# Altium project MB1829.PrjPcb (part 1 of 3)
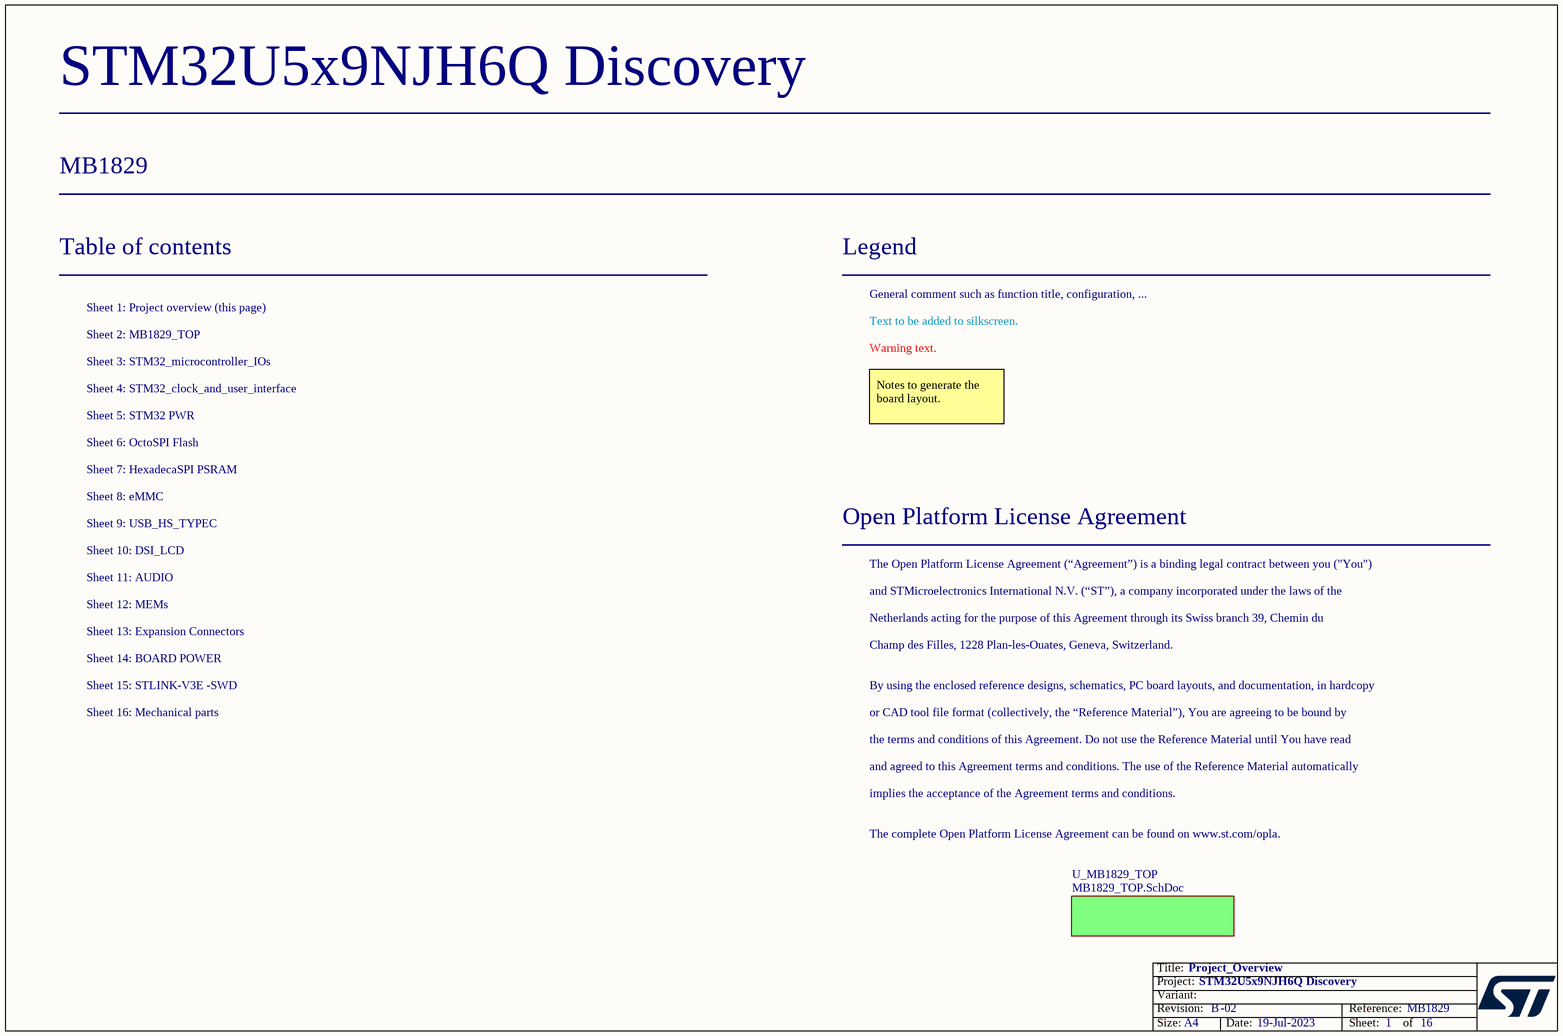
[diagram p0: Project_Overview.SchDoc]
Board_Assembly_Revision: 02; Board_Document_Date: 19-Jul-2023; Board_Name: STM32U5x9NJH6Q Discovery; Board_PCB_Revision: B; Board_Reference: MB1829
16 sheets, 473 parts. Net scope: flat (ports and power ports of the same name join across sheets).
Board file: MB1829.PcbDoc
Sheets:
  Project_Overview.SchDoc
    U_MB1829_TOP = MB1829_TOP.SchDoc
      U_EXPANSION_CONNECTORS = EXPANSION_CONNECTORS.SchDoc
      U_AUDIO = AUDIO.SchDoc
      U_BOARD_POWER = BOARD_POWER.SchDoc
      U_MCU_CLOCK_AND_USER_INTERFACE = MCU_CLOCK_AND_USER_INTERFACE.SchDoc
      U_MCU_IO = MCU_IO.SchDoc
      U_MCU_PWR = MCU_PWR.SchDoc
      U_MECHANICAL = MECHANICAL.SchDoc
      U_OCTOSPI_FLASH = OCTOSPI_FLASH.SchDoc
      U_ST_LINK_V3E = ST_LINK_V3E.SchDoc
      U_USBHS_TYPEC = USBHS_TYPEC.SchDoc
      U_eMMC = eMMC.SchDoc
      U_HEXADECASPI_PSRAM = HEXADECASPI_PSRAM.SchDoc
      U_DSI_LCD = DSI_LCD.SchDoc
      U_MEMS = MEMS.SchDoc

## Sheet Project_Overview.SchDoc: Project_Overview
size A4; Date: Not used; ApprovedBy: Not used; CheckedBy: Not used; Author: Not used; CompanyName: STMicroelectronics; DrawnBy: Not used; Engineer: Not used; Organization: Not used; Address1: Not used; Address2: Not used; Address3: Not used; Address4: Not used; DocumentNumber: Not used; Revision: Not used; SheetNumber: 1; SheetTotal: 16

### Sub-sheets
U_MB1829_TOP = MB1829_TOP.SchDoc: no entries

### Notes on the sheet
- Table of contents
- Sheet 1: Project overview (this page)
- Legend
- General comment such as function title, configuration, ...
- Sheet 2: MB1829_TOP
- Sheet 3: STM32_microcontroller_IOs
- Text to be added to silkscreen.
- Warning text.
- Sheet 4: STM32_clock_and_user_interface
- Sheet 6: OctoSPI Flash
- Sheet 5: STM32 PWR
- Notes to generate the board layout.
- Sheet 8: eMMC
- Sheet 7: HexadecaSPI PSRAM
- Sheet 10: DSI_LCD
- Sheet 11: AUDIO
- Sheet 9: USB_HS_TYPEC
- Open Platform License Agreement
- The Open Platform License Agreement (“Agreement”) is a binding legal contract between you ("You")
- Sheet 13: Expansion Connectors
- Sheet 12: MEMs
- and STMicroelectronics International N.V. (“ST”), a company incorporated under the laws of the
- Netherlands acting for the purpose of this Agreement through its Swiss branch 39, Chemin du
- Champ des Filles, 1228 Plan-les-Ouates, Geneva, Switzerland.
- Sheet 15: STLINK-V3E -SWD
- Sheet 16: Mechanical parts
- Sheet 14: BOARD POWER
- By using the enclosed reference designs, schematics, PC board layouts, and documentation, in hardcopy
- or CAD tool file format (collectively, the “Reference Material”), You are agreeing to be bound by
- the terms and conditions of this Agreement. Do not use the Reference Material until You have read
- and agreed to this Agreement terms and conditions. The use of the Reference Material automatically
- implies the acceptance of the Agreement terms and conditions.
- The complete Open Platform License Agreement can be found on www.st.com/opla.

## Sheet MB1829_TOP.SchDoc: MB1829 TOP
size A4; Date: Not used; ApprovedBy: Not used; CheckedBy: Not used; Author: Not used; CompanyName: STMicroelectronics; DrawnBy: Not used; Engineer: Not used; Organization: Not used; Address1: Not used; Address2: Not used; Address3: Not used; Address4: Not used; DocumentNumber: Not used; Revision: Not used; SheetNumber: 2; SheetTotal: 16
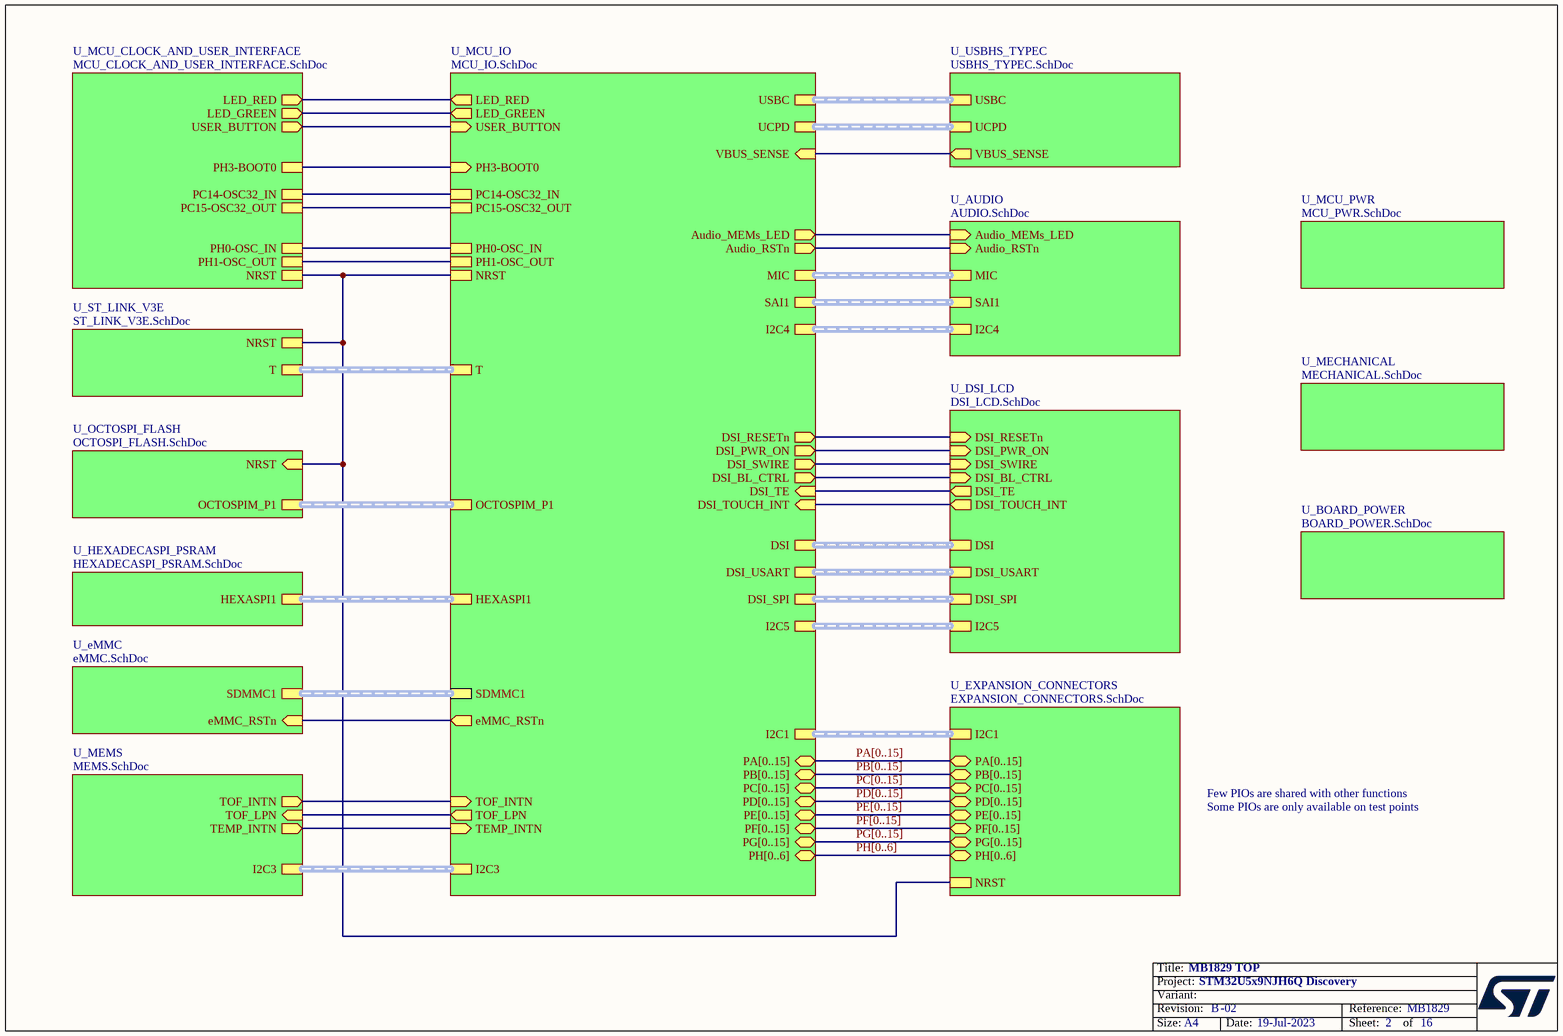
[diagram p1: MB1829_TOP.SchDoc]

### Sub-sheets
U_AUDIO = AUDIO.SchDoc: MIC (harness MIC), I2C4 (harness I2C4), SAI1 (harness SAI), Audio_RSTn (in), Audio_MEMs_LED (in)
U_BOARD_POWER = BOARD_POWER.SchDoc: no entries
U_DSI_LCD = DSI_LCD.SchDoc: DSI_RESETn (in), DSI_PWR_ON (in), DSI_SWIRE (in), DSI_BL_CTRL (in), DSI_TE (out), DSI_TOUCH_INT (out), DSI (harness DSI_LANES), I2C5 (harness I2C5), DSI_USART (harness DSI_USART), DSI_SPI (harness DSI_SPI)
U_eMMC = eMMC.SchDoc: eMMC_RSTn (in), SDMMC1 (harness eMMC)
U_EXPANSION_CONNECTORS = EXPANSION_CONNECTORS.SchDoc: NRST, I2C1 (harness I2C1), PC[0..15] (bidir), PA[0..15] (bidir), PB[0..15] (bidir), PD[0..15] (bidir), PE[0..15] (bidir), PH[0..6] (bidir), PF[0..15] (bidir), PG[0..15] (bidir)
U_HEXADECASPI_PSRAM = HEXADECASPI_PSRAM.SchDoc: HEXASPI1 (harness HEXASPI1)
U_MCU_CLOCK_AND_USER_INTERFACE = MCU_CLOCK_AND_USER_INTERFACE.SchDoc: NRST, PH3-BOOT0, PC14-OSC32_IN, PC15-OSC32_OUT, LED_RED (out), LED_GREEN (out), PH0-OSC_IN, PH1-OSC_OUT, USER_BUTTON (out)
U_MCU_IO = MCU_IO.SchDoc: PH3-BOOT0 (in), NRST, PH0-OSC_IN, PH1-OSC_OUT, PC14-OSC32_IN, PC15-OSC32_OUT, LED_RED (out), LED_GREEN (out), OCTOSPIM_P1 (harness OCTOSPI1), USBC (harness USBC), MIC (harness MIC), T (harness T), HEXASPI1 (harness HEXASPI1), SDMMC1 (harness eMMC), eMMC_RSTn (out), I2C4 (harness I2C4), SAI1 (harness SAI), USER_BUTTON (in), Audio_RSTn (out), I2C5 (harness I2C5), DSI_RESETn (out), DSI_PWR_ON (out), DSI_SWIRE (out), DSI_BL_CTRL (out), DSI_TE (in), DSI_TOUCH_INT (in), DSI_SPI (harness DSI_SPI), DSI_USART (harness DSI_USART), DSI (harness DSI_LANES), UCPD (harness UCPD_CTRL), VBUS_SENSE (in), PA[0..15] (bidir), PC[0..15] (bidir), PB[0..15] (bidir), PD[0..15] (bidir), PE[0..15] (bidir), PH[0..6] (bidir), PF[0..15] (bidir), PG[0..15] (bidir), I2C1 (harness I2C1), I2C3 (harness I2C3), TOF_INTN (in), TEMP_INTN (in), TOF_LPN (out), Audio_MEMs_LED (out)
U_MCU_PWR = MCU_PWR.SchDoc: no entries
U_MECHANICAL = MECHANICAL.SchDoc: no entries
U_MEMS = MEMS.SchDoc: I2C3 (harness I2C3), TOF_INTN (out), TOF_LPN (in), TEMP_INTN (out)
U_OCTOSPI_FLASH = OCTOSPI_FLASH.SchDoc: NRST (in), OCTOSPIM_P1 (harness OCTOSPI1)
U_ST_LINK_V3E = ST_LINK_V3E.SchDoc: NRST, T (harness T)
U_USBHS_TYPEC = USBHS_TYPEC.SchDoc: USBC (harness USBC), UCPD (harness UCPD_CTRL), VBUS_SENSE (out)

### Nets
(unnamed): sheet U_EXPANSION_CONNECTORS/NRST, sheet U_MCU_CLOCK_AND_USER_INTERFACE/NRST, sheet U_MCU_IO/NRST, sheet U_OCTOSPI_FLASH/NRST, sheet U_ST_LINK_V3E/NRST
(unnamed): sheet U_AUDIO/Audio_RSTn, sheet U_MCU_IO/Audio_RSTn  [a separate net that carries the same name]
(unnamed): sheet U_AUDIO/Audio_MEMs_LED, sheet U_MCU_IO/Audio_MEMs_LED  [a separate net that carries the same name]
(unnamed): sheet U_MCU_CLOCK_AND_USER_INTERFACE/PH3-BOOT0, sheet U_MCU_IO/PH3-BOOT0  [a separate net that carries the same name]
(unnamed): sheet U_MCU_CLOCK_AND_USER_INTERFACE/PC14-OSC32_IN, sheet U_MCU_IO/PC14-OSC32_IN  [a separate net that carries the same name]
(unnamed): sheet U_MCU_CLOCK_AND_USER_INTERFACE/PC15-OSC32_OUT, sheet U_MCU_IO/PC15-OSC32_OUT  [a separate net that carries the same name]
(unnamed): sheet U_MCU_CLOCK_AND_USER_INTERFACE/LED_RED, sheet U_MCU_IO/LED_RED  [a separate net that carries the same name]
(unnamed): sheet U_MCU_CLOCK_AND_USER_INTERFACE/LED_GREEN, sheet U_MCU_IO/LED_GREEN  [a separate net that carries the same name]
(unnamed): sheet U_MCU_CLOCK_AND_USER_INTERFACE/PH0-OSC_IN, sheet U_MCU_IO/PH0-OSC_IN  [a separate net that carries the same name]
(unnamed): sheet U_MCU_CLOCK_AND_USER_INTERFACE/PH1-OSC_OUT, sheet U_MCU_IO/PH1-OSC_OUT  [a separate net that carries the same name]
(unnamed): sheet U_MCU_CLOCK_AND_USER_INTERFACE/USER_BUTTON, sheet U_MCU_IO/USER_BUTTON  [a separate net that carries the same name]
(unnamed): sheet U_MCU_IO/eMMC_RSTn, sheet U_eMMC/eMMC_RSTn  [a separate net that carries the same name]
(unnamed): sheet U_MCU_IO/DSI_RESETn, sheet U_DSI_LCD/DSI_RESETn  [a separate net that carries the same name]
(unnamed): sheet U_MCU_IO/DSI_PWR_ON, sheet U_DSI_LCD/DSI_PWR_ON  [a separate net that carries the same name]
(unnamed): sheet U_MCU_IO/DSI_SWIRE, sheet U_DSI_LCD/DSI_SWIRE  [a separate net that carries the same name]
(unnamed): sheet U_MCU_IO/DSI_BL_CTRL, sheet U_DSI_LCD/DSI_BL_CTRL  [a separate net that carries the same name]
(unnamed): sheet U_MCU_IO/DSI_TE, sheet U_DSI_LCD/DSI_TE  [a separate net that carries the same name]
(unnamed): sheet U_MCU_IO/DSI_TOUCH_INT, sheet U_DSI_LCD/DSI_TOUCH_INT  [a separate net that carries the same name]
(unnamed): sheet U_MCU_IO/VBUS_SENSE, sheet U_USBHS_TYPEC/VBUS_SENSE  [a separate net that carries the same name]
(unnamed): sheet U_MCU_IO/TOF_INTN, sheet U_MEMS/TOF_INTN  [a separate net that carries the same name]
(unnamed): sheet U_MCU_IO/TEMP_INTN, sheet U_MEMS/TEMP_INTN  [a separate net that carries the same name]
(unnamed): sheet U_MCU_IO/TOF_LPN, sheet U_MEMS/TOF_LPN  [a separate net that carries the same name]

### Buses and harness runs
bus PA[0..15] = sheet U_EXPANSION_CONNECTORS/PA[0..15] = sheet U_MCU_IO/PA[0..15]
bus PB[0..15] = sheet U_EXPANSION_CONNECTORS/PB[0..15] = sheet U_MCU_IO/PB[0..15]
bus PC[0..15] = sheet U_EXPANSION_CONNECTORS/PC[0..15] = sheet U_MCU_IO/PC[0..15]
bus PD[0..15] = sheet U_EXPANSION_CONNECTORS/PD[0..15] = sheet U_MCU_IO/PD[0..15]
bus PE[0..15] = sheet U_EXPANSION_CONNECTORS/PE[0..15] = sheet U_MCU_IO/PE[0..15]
bus PF[0..15] = sheet U_EXPANSION_CONNECTORS/PF[0..15] = sheet U_MCU_IO/PF[0..15]
bus PG[0..15] = sheet U_EXPANSION_CONNECTORS/PG[0..15] = sheet U_MCU_IO/PG[0..15]
bus PH[0..6] = sheet U_EXPANSION_CONNECTORS/PH[0..6] = sheet U_MCU_IO/PH[0..6]
harness sheet U_AUDIO/I2C4 = sheet U_MCU_IO/I2C4
harness sheet U_AUDIO/MIC = sheet U_MCU_IO/MIC
harness sheet U_AUDIO/SAI1 = sheet U_MCU_IO/SAI1
harness sheet U_DSI_LCD/DSI = sheet U_MCU_IO/DSI
harness sheet U_DSI_LCD/DSI_SPI = sheet U_MCU_IO/DSI_SPI
harness sheet U_DSI_LCD/DSI_USART = sheet U_MCU_IO/DSI_USART
harness sheet U_DSI_LCD/I2C5 = sheet U_MCU_IO/I2C5
harness sheet U_eMMC/SDMMC1 = sheet U_MCU_IO/SDMMC1
harness sheet U_EXPANSION_CONNECTORS/I2C1 = sheet U_MCU_IO/I2C1
harness sheet U_HEXADECASPI_PSRAM/HEXASPI1 = sheet U_MCU_IO/HEXASPI1
harness sheet U_MCU_IO/I2C3 = sheet U_MEMS/I2C3
harness sheet U_MCU_IO/OCTOSPIM_P1 = sheet U_OCTOSPI_FLASH/OCTOSPIM_P1
harness sheet U_MCU_IO/T = sheet U_ST_LINK_V3E/T
harness sheet U_MCU_IO/UCPD = sheet U_USBHS_TYPEC/UCPD
harness sheet U_MCU_IO/USBC = sheet U_USBHS_TYPEC/USBC

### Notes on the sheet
- Few PIOs are shared with other functions
- Some PIOs are only available on test points

## Sheet EXPANSION_CONNECTORS.SchDoc: Expansion Connectors
size A3; Date: Not used; ApprovedBy: Not used; CheckedBy: Not used; Author: Not used; CompanyName: STMicroelectronics; DrawnBy: Not used; Engineer: Not used; Organization: Not used; Address1: Not used; Address2: Not used; Address3: Not used; Address4: Not used; DocumentNumber: Not used; Revision: Not used; SheetNumber: 13; SheetTotal: 16
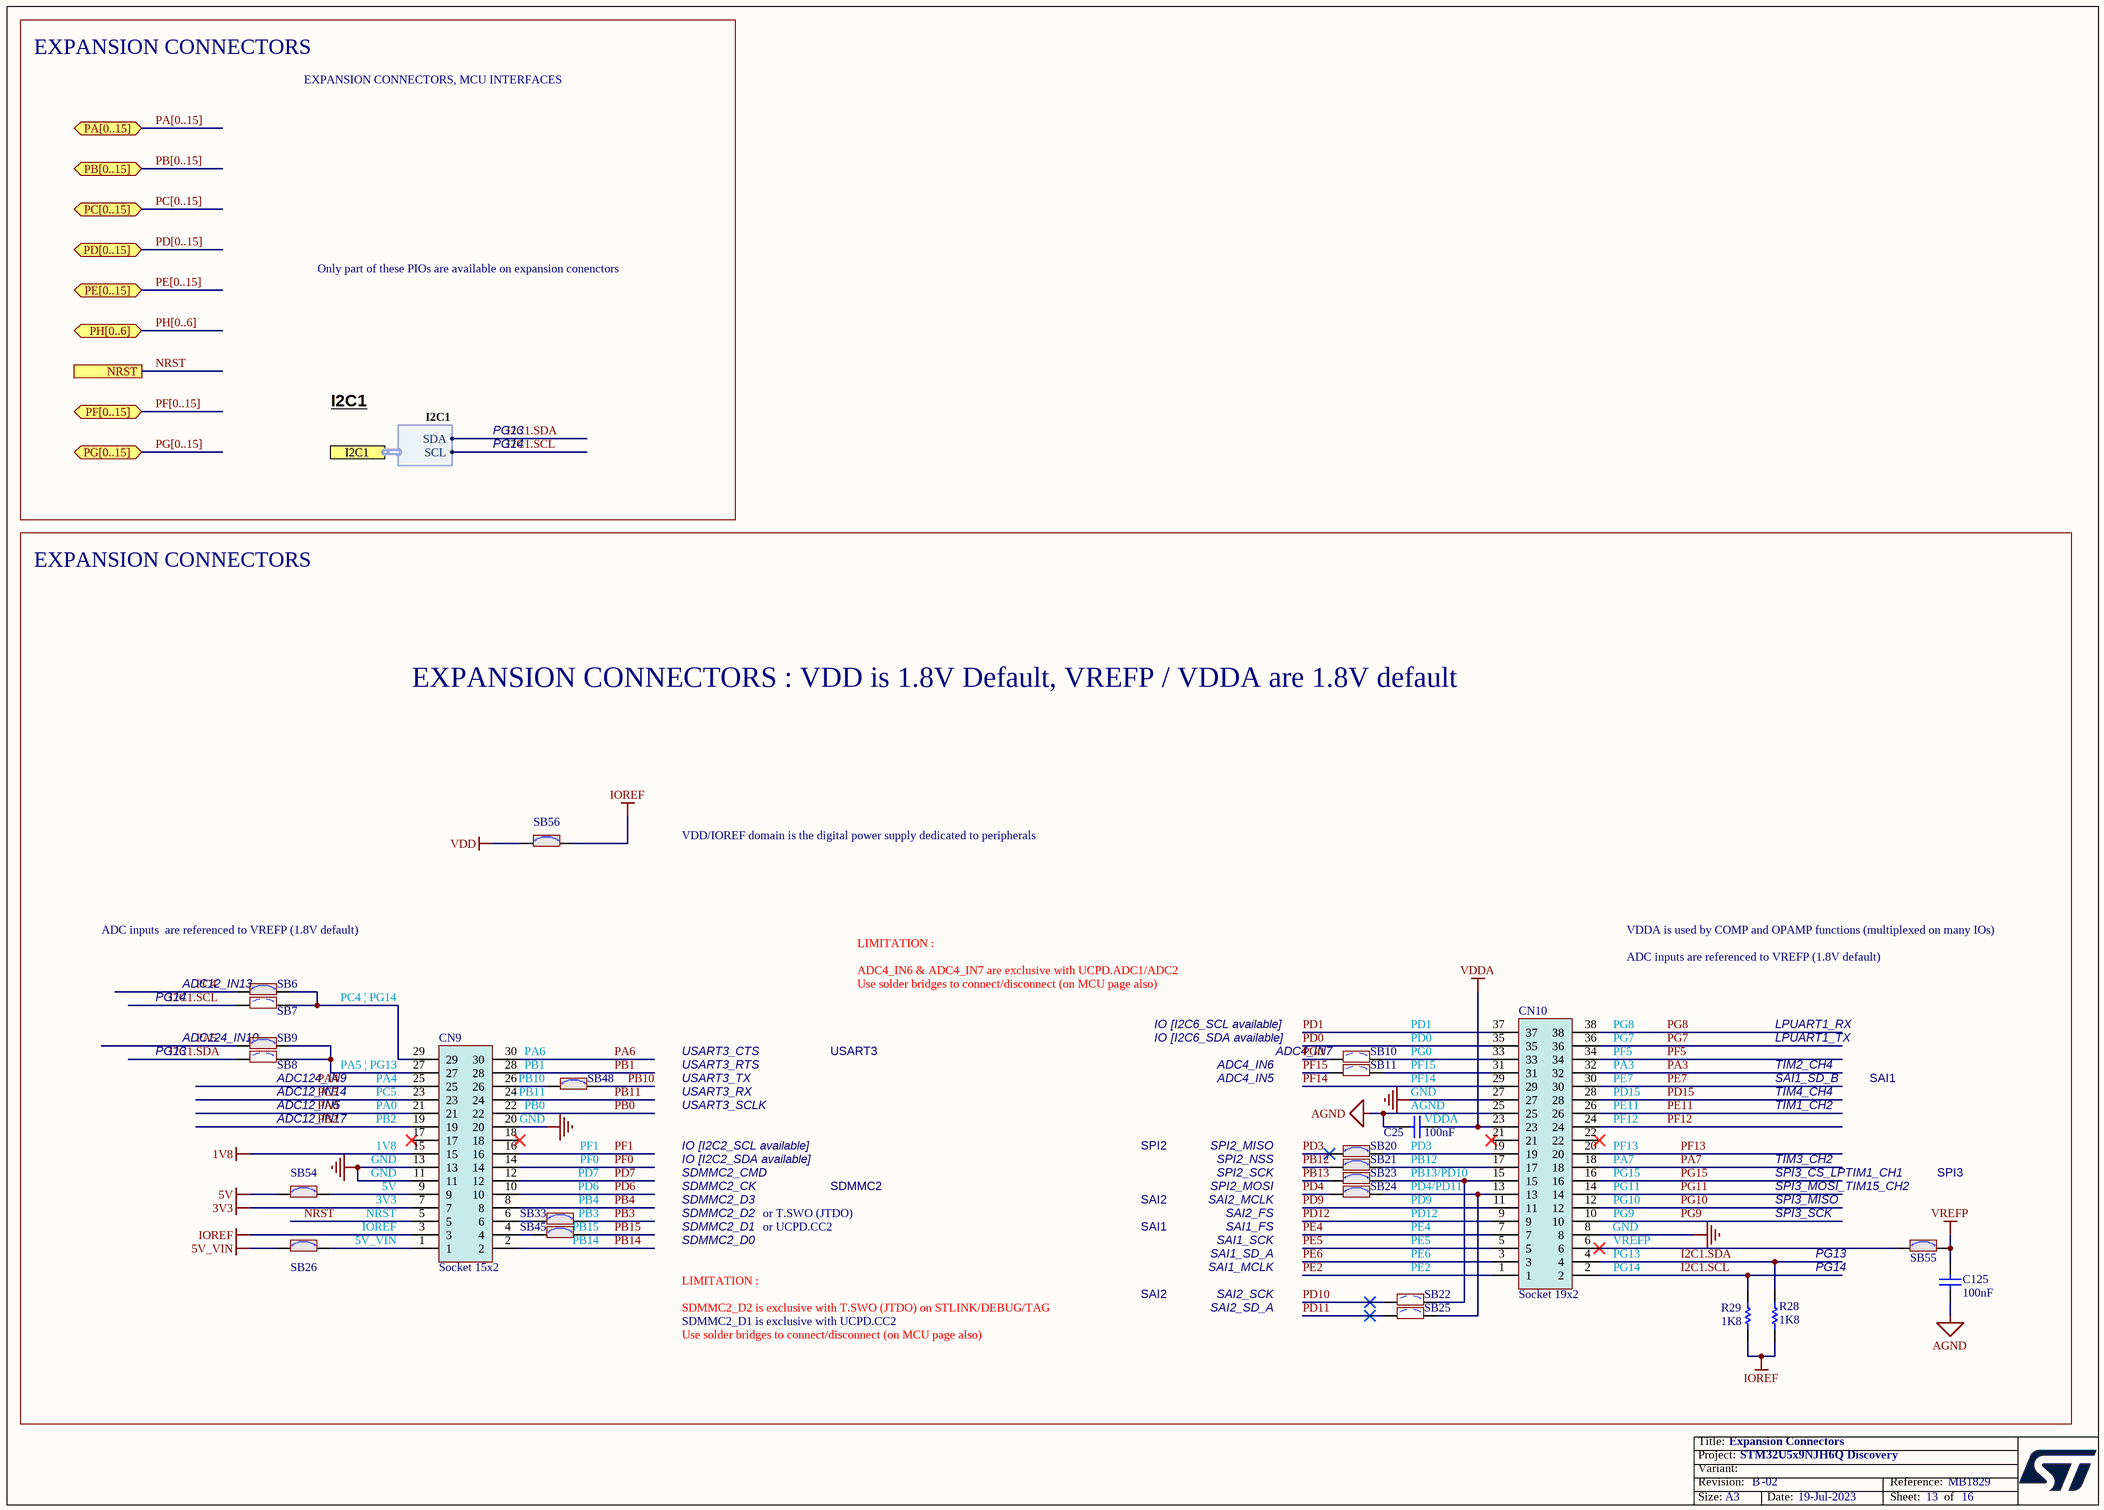
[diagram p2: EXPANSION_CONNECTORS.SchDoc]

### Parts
C25  value 100nF  [C0603]  (hidden comment: Capacitor)
C125  value 100nF  [C0603]  (hidden comment: Capacitor)
CN9  Socket 15x2  [CON_SAMTEC_SSW-115-21-F-D]
CN10  Socket 19x2  [CON_SAMTEC_SSW-119-21-F-D]
R28  value 1K8  [R0402]  (hidden comment: Resistor)
R29  value 1K8  [R0402]  (hidden comment: Resistor)
SB6  SB_ON  [SOLDER-BRIDGE_R0402-0R]  (value not drawn)
SB7  SB_OFF  [SOLDER-BRIDGE_R0402-0R]  (value not drawn)
SB8  SB_OFF  [SOLDER-BRIDGE_R0402-0R]  (value not drawn)
SB9  SB_ON  [SOLDER-BRIDGE_R0402-0R]  (value not drawn)
SB10  SB_OFF  [SOLDER-BRIDGE_R0402-0R]  (value not drawn)
SB11  SB_OFF  [SOLDER-BRIDGE_R0402-0R]  (value not drawn)
SB20  SB_ON  [SOLDER-BRIDGE_R0402-0R]  (value not drawn)
SB21  SB_ON  [SOLDER-BRIDGE_R0402-0R]  (value not drawn)
SB22  SB_OFF  [SOLDER-BRIDGE_R0402-0R]  (value not drawn)
SB23  SB_ON  [SOLDER-BRIDGE_R0402-0R]  (value not drawn)
SB24  SB_ON  [SOLDER-BRIDGE_R0402-0R]  (value not drawn)
SB25  SB_OFF  [SOLDER-BRIDGE_R0402-0R]  (value not drawn)
SB26  SB_ON  [SOLDER-BRIDGE_R0402-0R]  (value not drawn)
SB33  SB_ON  [SOLDER-BRIDGE_R0402-0R]  (value not drawn)
SB45  SB_ON  [SOLDER-BRIDGE_R0402-0R]  (value not drawn)
SB48  SB_ON  [SOLDER-BRIDGE_R0402-0R]  (value not drawn)
SB54  SB_ON  [SOLDER-BRIDGE_R0402-0R]  (value not drawn)
SB55  SB_ON  [SOLDER-BRIDGE_R0402-0R]  (value not drawn)
SB56  SB_ON  [SOLDER-BRIDGE_R0402-0R]  (value not drawn)

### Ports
I2C1 (harness I2C1), NRST, PA[0..15] (bidir), PB[0..15] (bidir), PC[0..15] (bidir), PD[0..15] (bidir), PE[0..15] (bidir), PF[0..15] (bidir), PG[0..15] (bidir), PH[0..6] (bidir)

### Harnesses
I2C1: SDA, SCL

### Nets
1V8: CN9.15
3V3: CN9.7
5V: SB54.1
5V_VIN: SB26.1
AGND: C25.1 C125.1 CN10.25
GND: CN9.11 CN9.13 CN9.20 CN10.8 CN10.27
IOREF: CN9.3 R28.2 R29.2 SB56.2
VDD: SB56.1
VDDA: C25.2 CN10.23
VREFP: C125.2 SB55.2
I2C1.SCL: CN10.2 R29.1 SB7.1 ; port I2C1.SCL
I2C1.SDA: CN10.4 R28.1 SB8.1 ; port I2C1.SDA
NRST: CN9.5 ; port NRST
PA0: CN9.21
PA3: CN10.32
PA4: CN9.25
PA5: SB9.1
PA6: CN9.30
PA7: CN10.18
PB0: CN9.22
PB1: CN9.28
PB2: CN9.19
PB3: SB33.2
PB4: CN9.8
PB10: SB48.2
PB11: CN9.24
PB12: SB21.1
PB13: SB23.1  [project net DSI_SPI_CLK]
PB14: CN9.2
PB15: SB45.2
PC4: SB6.1
PC5: CN9.23
PD0: CN10.35
PD1: CN10.37
PD3: SB20.1
PD4: SB24.1  [project net DSI_SPI_MOSI]
PD6: CN9.10
PD7: CN9.12
PD9: CN10.11
PD10: SB22.1
PD11: SB25.1  [project net DSI_SPI_D/CX]
PD12: CN10.9
PD15: CN10.28
PE2: CN10.1
PE4: CN10.7
PE5: CN10.5
PE6: CN10.3
PE7: CN10.30
PE11: CN10.26
PF0: CN9.14
PF1: CN9.16
PF5: CN10.34
PF12: CN10.24
PF13: CN10.20
PF14: CN10.29
PF15: SB11.1
PG0: SB10.1
PG7: CN10.36
PG8: CN10.38
PG9: CN10.10
PG10: CN10.12
PG11: CN10.14
PG15: CN10.16
NetCN9_1: CN9.1 SB26.2
NetCN9_4: CN9.4 SB45.1
NetCN9_6: CN9.6 SB33.1
NetCN9_9: CN9.9 SB54.2
NetCN9_26: CN9.26 SB48.1
NetCN9_27: CN9.27 SB8.2 SB9.2
NetCN9_29: CN9.29 SB6.2 SB7.2
NetCN10_6: CN10.6 SB55.1
NetCN10_13: CN10.13 SB24.2 SB25.2
NetCN10_15: CN10.15 SB22.2 SB23.2
NetCN10_17: CN10.17 SB21.2
NetCN10_19: CN10.19 SB20.2
NetCN10_31: CN10.31 SB11.2
NetCN10_33: CN10.33 SB10.2

Not connected (* = marked no-connect by the designer): CN9 17* 18*; CN10 21* 22*

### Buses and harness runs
bus PA[0..15] = port PA[0..15]
bus PB[0..15] = port PB[0..15]
bus PC[0..15] = port PC[0..15]
bus PD[0..15] = port PD[0..15]
bus PE[0..15] = port PE[0..15]
bus PF[0..15] = port PF[0..15]
bus PG[0..15] = port PG[0..15]
bus PH[0..6] = port PH[0..6]

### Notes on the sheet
- EXPANSION CONNECTORS
- EXPANSION CONNECTORS, MCU INTERFACES
- Only part of these PIOs are available on expansion conenctors
- I2C1
- PG13
- PG14
- EXPANSION CONNECTORS : VDD is 1.8V Default, VREFP / VDDA are 1.8V default
- VDD/IOREF domain is the digital power supply dedicated to peripherals
- ADC inputs  are referenced to VREFP (1.8V default)
- ADC12_IN13
- ADC4_IN6 & ADC4_IN7 are exclusive with UCPD.ADC1/ADC2
- Use solder bridges to connect/disconnect (on MCU page also)
- LIMITATION :
- ADC inputs are referenced to VREFP (1.8V default)
- VDDA is used by COMP and OPAMP functions (multiplexed on many IOs)
- ADC124_IN10
- PC4 ¦ PG14
- PA6
- USART3_CTS
- USART3
- IO [I2C6_SDA available]
- IO [I2C6_SCL available]
- ADC4_IN7
- PG0
- PD0
- PD1
- (near CN10) PF5
- (near CN10) PG7
- (near CN10) PG8
- LPUART1_TX
- LPUART1_RX
- ADC12_IN17
- ADC12_IN5
- ADC12_IN14
- (near SB8) ADC124_IN9
- (near CN9) PB2
- (near CN9) PA0
- (near CN9) PC5
- (near CN9) PA4
- PA5 ¦ PG13
- (near SB48) PB0
- (near SB48) PB11
- (near SB48) PB10
- (near SB48) PB1
- GND
- USART3_TX
- USART3_RX
- USART3_SCLK
- USART3_RTS
- ADC4_IN5
- ADC4_IN6
- PF14
- PF15
- (near C25) AGND
- (near C25) VDDA
- (near CN10) PF12
- (near CN10) PE11
- (near CN10) PD15
- (near CN10) PE7
- (near CN10) PA3
- TIM1_CH2
- TIM4_CH4
- TIM2_CH4
- SAI1_SD_B
- SAI1
- (near CN9) 5V
- (near CN9) GND
- (near CN9) 1V8
- PD6
- PD7
- PF0
- PF1
- SDMMC2_CK
- SDMMC2_CMD
- IO [I2C2_SDA available]
- IO [I2C2_SCL available]
- SDMMC2
- SPI2
- SPI2_MISO
- SPI2_NSS
- SPI2_MOSI
- SPI2_SCK
- PD4/PD11
- PB13/PD10
- PB12
- (near C25) PD3
- (near CN10) PF13
- (near CN10) PA7
- (near CN10) PG15
- (near CN10) PG11
- TIM3_CH2
- SPI3_CS_LPTIM1_CH1
- SPI3_MOSI_TIM15_CH2
- SPI3
- IOREF
- NRST
- 3V3
- 5V_VIN
- (near SB33) PB4
- PB3
- (near SB45) PB14
- PB15
- SDMMC2_D0
- SDMMC2_D1
- SDMMC2_D2
- SDMMC2_D3
- or T.SWO (JTDO)
- or UCPD.CC2
- SAI2
- SAI1_SD_A
- SAI1_SCK
- SAI1_FS
- SAI2_FS
- SAI2_MCLK
- PE6
- PE5
- PE4
- PD12
- PD9
- (near CN10) VREFP
- (near CN10) PG10
- (near CN10) PG9
- (near CN10) PG13
- (near CN10) GND
- SPI3_SCK
- SPI3_MISO
- SDMMC2_D2 is exclusive with T.SWO (JTDO) on STLINK/DEBUG/TAG
- SDMMC2_D1 is exclusive with UCPD.CC2
- SAI1_MCLK
- SAI2_SD_A
- SAI2_SCK
- PE2
- (near CN10) PG14

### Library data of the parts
C25 C125 = MCD-00211: Capacitor, MLCC, 100nF, 16V, X7R, +/-10%, 0603, T=0.8mm; Manufacturer_Part_Number: CC0603KRX7R7BB104; Manufacturer: YAGEO; Part_Preference: Recommended; Order_Code_RS: 669-8763; Component_Country_Of_Origin: China
CN9 = MCD-02943: Socket, 15x2, 2.54mm, VR, TH, T=8.51mm/2.64mm; Part_Type: Connector; Part_Preference: Recommended; Manufacturer: SAMTEC; Manufacturer_Part_Number: SSW-115-21-F-D; Partial_Alternate_Internal_Part_Number: MCD-02945; ShowFields: YES; ID: 5059
CN10 = MCD-02944: Socket, 19x2, 2.54mm, VR, TH, T=8.51mm/2.64mm; Part_Type: Connector; Part_Preference: Recommended; Manufacturer: SAMTEC; Manufacturer_Part_Number: SSW-119-21-F-D; Partial_Alternate_Internal_Part_Number: MCD-02946; ShowFields: YES; ID: 5060
R28 R29 = MCD-00409: Resistor, 1K8, 0402, +/-1%, 1/16W; Manufacturer_Part_Number: RC0402FR-071K8L; Manufacturer: YAGEO; Part_Preference: Recommended; Component_Country_Of_Origin: China
SB6 SB9 SB20 SB21 SB23 SB24 SB26 SB33 SB45 SB48 SB54-SB56 = MCD-01618: Solder Bridge 0402 ON; Part_Type: Misc; Manufacturer_Part_Number: RC0402JR-070RL; Manufacturer: YAGEO; Part_Preference: Recommended; Order_Code_RS: 618-5804; Component_Country_Of_Origin: China
SB7 SB8 = MCD-02162: Solder Bridge 0402 OFF; Part_Type: Misc; Manufacturer_Part_Number: RC0402JR-070RL; Manufacturer: YAGEO; Part_Preference: Recommended; Order_Code_RS: 618-5804
SB10 SB11 SB22 SB25 = MCD-02162: Solder Bridge 0402 OFF; Part_Type: Misc; Manufacturer_Part_Number: RC0402JR-070RL; Manufacturer: YAGEO; Part_Preference: Recommended; Order_Code_RS: 618-5804; Component_Country_Of_Origin: China

## Sheet AUDIO.SchDoc: AUDIO
size A4; Date: Not used; ApprovedBy: Not used; CheckedBy: Not used; Author: Not used; CompanyName: STMicroelectronics; DrawnBy: Not used; Engineer: Not used; Organization: Not used; Address1: Not used; Address2: Not used; Address3: Not used; Address4: Not used; DocumentNumber: Not used; Revision: Not used; SheetNumber: 11; SheetTotal: 16
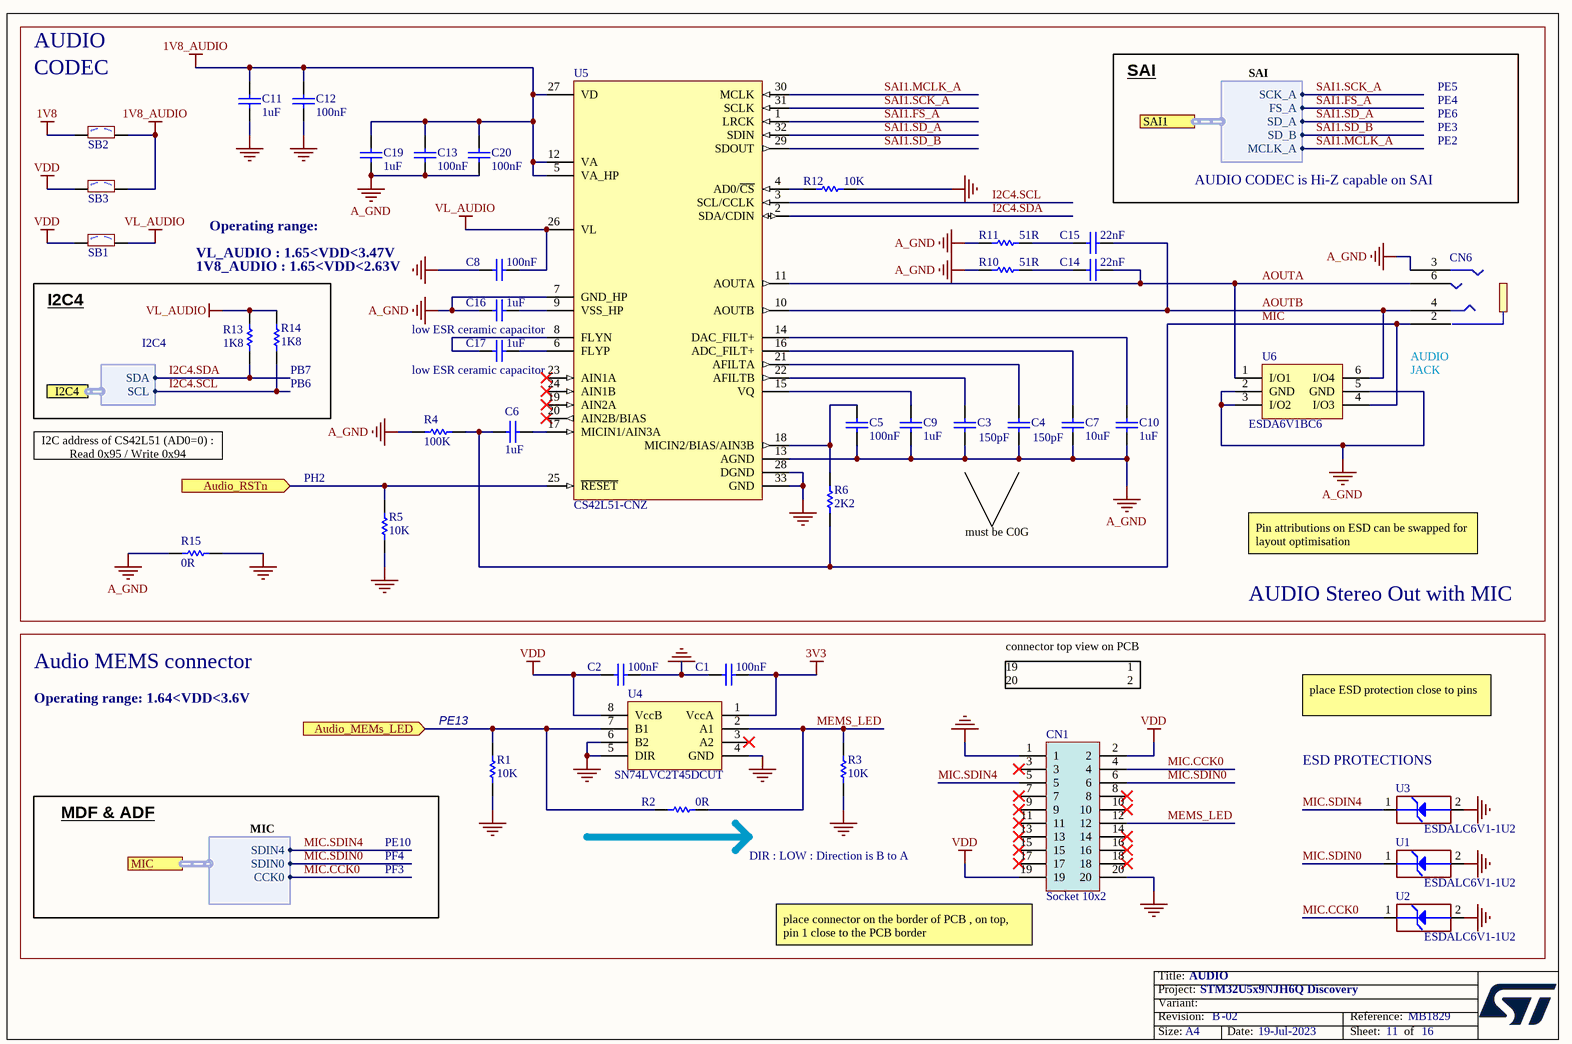
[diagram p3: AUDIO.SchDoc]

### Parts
C1  value 100nF  [C0402]  (hidden comment: Capacitor)
C2  value 100nF  [C0402]  (hidden comment: Capacitor)
C3  value 150pF  [C0603]  (hidden comment: Capacitor)
C4  value 150pF  [C0603]  (hidden comment: Capacitor)
C5  value 100nF  [C0402]  (hidden comment: Capacitor)
C6  value 1uF  [C0402]  (hidden comment: Capacitor)
C7  value 10uF  [C0603]  (hidden comment: Capacitor)
C8  value 100nF  [C0402]  (hidden comment: Capacitor)
C9  value 1uF  [C0402]  (hidden comment: Capacitor)
C10  value 1uF  [C0402]  (hidden comment: Capacitor)
C11  value 1uF  [C0402]  (hidden comment: Capacitor)
C12  value 100nF  [C0402]  (hidden comment: Capacitor)
C13  value 100nF  [C0402]  (hidden comment: Capacitor)
C14  value 22nF  [C0402]  (hidden comment: Capacitor)
C15  value 22nF  [C0402]  (hidden comment: Capacitor)
C16  value 1uF  [C0603]  (hidden comment: Capacitor)
C17  value 1uF  [C0603]  (hidden comment: Capacitor)
C19  value 1uF  [C0402]  (hidden comment: Capacitor)
C20  value 100nF  [C0402]  (hidden comment: Capacitor)
CN1  Socket 10x2  [CON_FCI_20021311-XXX20XXLF]
CN6  Jack_PJ3028B-3_4P  [CON_PHONE-JACK-3P5_HY_PJ3028B]  (value not drawn)
R1  value 10K  [R0402]  (hidden comment: Resistor)
R2  value 0R  [R0402]  (hidden comment: Resistor)
R3  value 10K  [R0402]  (hidden comment: Resistor)
R4  value 100K  [R0402]  (hidden comment: Resistor)
R5  value 10K  [R0402]  (hidden comment: Resistor)
R6  value 2K2  [R0402]  (hidden comment: Resistor)
R10  value 51R  [R0402]  (hidden comment: Resistor)
R11  value 51R  [R0402]  (hidden comment: Resistor)
R12  value 10K  [R0402]  (hidden comment: Resistor)
R13  value 1K8  [R0402]  (hidden comment: Resistor)
R14  value 1K8  [R0402]  (hidden comment: Resistor)
R15  value 0R  [R0402]  (hidden comment: Resistor)
SB1  SB_OFF  [SOLDER-BRIDGE_R0402-0R]  (value not drawn)
SB2  SB_OFF  [SOLDER-BRIDGE_R0402-0R]  (value not drawn)
SB3  SB_OFF  [SOLDER-BRIDGE_R0402-0R]  (value not drawn)
U1  value ESDALC6V1-1U2  [ESD_ST0201]  (hidden comment: ESD-TRANSIL)
U2  value ESDALC6V1-1U2  [ESD_ST0201]  (hidden comment: ESD-TRANSIL)
U3  value ESDALC6V1-1U2  [ESD_ST0201]  (hidden comment: ESD-TRANSIL)
U4  SN74LVC2T45DCUT  [ICC_VSSOP8_DCU_R-PDSO-G8_2X2P30_P050]
U5  CS42L51-CNZ  [ICC_QFN32-EPAD_5X5_P050]
U6  ESDA6V1BC6  [ESD_SOT23-6L]

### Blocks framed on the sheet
I2C4: R13 R14
Audio MEMS connector: C1 C2 CN1 R1-R3 U1-U4

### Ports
Audio_MEMs_LED (in), Audio_RSTn (in), I2C4 (harness I2C4), MIC (harness MIC), SAI1 (harness SAI)

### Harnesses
I2C4: SDA, SCL
MIC: SDIN0, CCK0, SDIN4
SAI: SD_B, FS_A, SD_A, SCK_A, MCLK_A

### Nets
1V8: SB2.1
1V8_AUDIO: C11.2 C12.2 C13.2 C19.2 C20.2 SB2.2 SB3.2 U5.5(VA_HP) U5.12(VA) U5.27(VD)
3V3: C1.2 U4.1(VccA)
A_GND: C3.1 C4.1 C5.1 C7.1 C9.1 C10.1 C13.1 C16.1 C19.1 C20.1 CN6.3 R4.1 R10.1 R11.1 R15.1 U5.7(GND_HP) U5.13(AGND) U6.2(GND) U6.3(I/O2) U6.5(GND)
GND: C1.1 C2.2 C8.2 C11.1 C12.1 CN1.1 CN1.20 R1.1 R3.1 R5.1 R12.2 R15.2 U1.2(GND) U2.2(GND) U3.2(GND) U4.4(GND) U4.5(DIR) U4.6(B2) U5.28(DGND) U5.33(GND)
VDD: C2.1 CN1.2 CN1.19 SB1.1 SB3.1 U4.8(VccB)
VL_AUDIO: C8.1 R13.2 R14.2 SB1.2 U5.26(VL)
AOUTA: C14.2 CN6.6 U5.11(AOUTA) U6.1(I/O1)
AOUTB: C15.2 CN6.4 U5.10(AOUTB) U6.6(I/O4)
AUDIO_MEMs_LED: R1.2 R2.1 U4.7(B1) ; port Audio_MEMs_LED
Audio_RSTn: R5.2 U5.25(~{RESET}) ; port Audio_RSTn
I2C4.SCL: R14.1 U5.3(SCL/CCLK) ; port I2C4.SCL
I2C4.SDA: R13.1 U5.2(SDA/CDIN) ; port I2C4.SDA
MEMS_LED: CN1.12 R2.2 R3.2 U4.2(A1)
MIC: C6.1 CN6.2 R4.2 R6.1 U6.4(I/O3)
MIC.CCK0: CN1.4 U2.1(IO1) ; port MIC.CCK0
MIC.SDIN0: CN1.6 U1.1(IO1) ; port MIC.SDIN0
MIC.SDIN4: CN1.5 U3.1(IO1) ; port MIC.SDIN4
SAI1.FS_A: U5.1(LRCK) ; port SAI1.FS_A  [project net PE4]
SAI1.MCLK_A: U5.30(MCLK) ; port SAI1.MCLK_A  [project net PE2]
SAI1.SCK_A: U5.31(SCLK) ; port SAI1.SCK_A  [project net PE5]
SAI1.SD_A: U5.32(SDIN) ; port SAI1.SD_A  [project net PE6]
SAI1.SD_B: U5.29(SDOUT) ; port SAI1.SD_B
NetC3_2: C3.2 U5.22(AFILTB)
NetC4_2: C4.2 U5.21(AFILTA)
NetC5_2: C5.2 R6.2 U5.18(MICIN2/BIAS/AIN3B)
NetC6_2: C6.2 U5.17(MICIN1/AIN3A)
NetC7_2: C7.2 U5.16(ADC_FILT+)
NetC9_2: C9.2 U5.15(VQ)
NetC10_2: C10.2 U5.14(DAC_FILT+)
NetC14_1: C14.1 R10.2
NetC15_1: C15.1 R11.2
NetC16_2: C16.2 U5.9(VSS_HP)
NetC17_1: C17.1 U5.8(FLYN)
NetC17_2: C17.2 U5.6(FLYP)
NetR12_1: R12.1 U5.4(AD0/~{CS})

Not connected (* = marked no-connect by the designer): CN1 3* 7* 8* 9* 10* 11* 13* 14* 15* 16* 17* 18*; U4 3(A2)*; U5 19(AIN2A)* 20(AIN2B/BIAS)* 23(AIN1A)* 24(AIN1B)*

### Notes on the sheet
- AUDIO
- CODEC
- SAI
- PE4
- PE5
- PE6
- AUDIO CODEC is Hi-Z capable on SAI
- PE2
- PE3
- Operating range:
- (near C8) VL_AUDIO : 1.65<VDD<3.47V
- 1V8_AUDIO : 1.65<VDD<2.63V
- PB6
- (near R14) PB7
- low ESR ceramic capacitor
- (near CN6) AUDIO
- JACK
- I2C address of CS42L51 (AD0=0) :
  Read 0x95 / Write 0x94
- PH2
- must be C0G
- Pin attributions on ESD can be swapped for layout optimisation
- connector top view on PCB
- AUDIO Stereo Out with MIC
- Operating range: 1.64<VDD<3.6V
- (near R1) PE13
- 19
- 20
- 1
- 2
- place ESD protection close to pins
- (near U3) ESD PROTECTIONS
- MDF & ADF
- PF4
- PE10
- (near R2) DIR : LOW : Direction is B to A
- PF3
- (near CN1) place connector on the border of PCB , on top, pin 1 close to the PCB border

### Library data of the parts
C1 C2 C5 C8 C12 C13 C20 = MCD-00006: Capacitor, MLCC, 100nF, 16V, X7R, +/-10%, 0402, T=0.5mm; Manufacturer_Part_Number: CC0402KRX7R7BB104; Manufacturer: YAGEO; Part_Preference: Recommended; Order_Code_RS: 616-9701; Component_Country_Of_Origin: China
C3 C4 = MCD-00304: Capacitor, MLCC, 150pF, 50V, COG, +/-5%, 0603, T=0.8mm; Manufacturer_Part_Number: CC0603JRNPO9BN151; Manufacturer: YAGEO; BMS_Part_Number: 9142051; Part_Preference: Recommended; Component_Country_Of_Origin: China
C6 C9-C11 C19 = MCD-01722: Capacitor, MLCC, 1uF, 10V, X5R, +/-10%, 0402, T=0.5mm; Manufacturer_Part_Number: CC0402KRX5R6BB105; Manufacturer: YAGEO; Part_Preference: Recommended; Component_Country_Of_Origin: China
C7 = MCD-00243: Capacitor, MLCC, 10uF, 6V3, X5R, +/-10%, 0603, T=0.8mm; Manufacturer_Part_Number: CC0603KRX5R5BB106; Manufacturer: YAGEO; Part_Preference: Recommended; Component_Country_Of_Origin: China
C14 C15 = MCD-00202: Capacitor, MLCC, 22nF, 16V, X7R, +/-10%, 0402, T=0.5mm; Manufacturer_Part_Number: CC0402KRX7R7BB223; Manufacturer: YAGEO; Part_Preference: Recommended; Component_Country_Of_Origin: China
C16 C17 = MCD-00010: Capacitor, MLCC, 1uF, 16V, X5R, +/-10%, 0603, T=0.8mm; Manufacturer_Part_Number: CC0603KRX5R7BB105; Manufacturer: YAGEO; Part_Preference: Recommended; Component_Country_Of_Origin: China
CN1 = MCD-00147: Socket, 10x2, 1.27mm, VR, TH, T=4.30mm/2.40mm; Part_Type: Connector; Part_Preference: Recommended; Manufacturer: AMPHENOL ICC; Manufacturer_Part_Number: 20021311-00020T4LF; Order_Code_RS: 170-8859; Component_Country_Of_Origin: China
CN6 = MCD-00263: Jack_ Socket-Stereo, 3.5mm, 4 pins, RA, SMD, T=5mm; Part_Type: Connector; Manufacturer: QIAOD; Part_Preference: Recommended; Value: Jack_ Socket-Stereo_PJ3028B-3_4P; Component_Country_Of_Origin: Unknown
R1 R3 R5 R12 = MCD-00053: Resistor, 10K, 0402, +/-1%, 1/16W; Manufacturer_Part_Number: RC0402FR-0710KL; Manufacturer: YAGEO; BMS_Part_Number: 9131590; Part_Preference: Recommended; Component_Country_Of_Origin: China
R2 R15 = MCD-00052: Resistor, 0R, 0402, +/-5%, 1/16W; Manufacturer_Part_Number: RC0402JR-070RL; Manufacturer: YAGEO; Part_Preference: Recommended; Order_Code_RS: 618-5804; Component_Country_Of_Origin: China
R4 = MCD-00059: Resistor, 100K, 0402, +/-1%, 1/16W; Manufacturer_Part_Number: RC0402FR-07100KL; Manufacturer: YAGEO; Part_Preference: Recommended; Component_Country_Of_Origin: China; ShowFields: YES; ID: 2533
R6 = MCD-00057: Resistor, 2K2, 0402, +/-1%, 1/16W; Manufacturer_Part_Number: RC0402FR-072K2L; Manufacturer: YAGEO; Part_Preference: Recommended; Component_Country_Of_Origin: China
R10 R11 = MCD-00485: Resistor, 51R, 0402, +/-1%, 1/16W; Manufacturer_Part_Number: RC0402FR-0751RL; Manufacturer: YAGEO; Part_Preference: Recommended; Component_Country_Of_Origin: China
R13 R14 = MCD-00409: as R28 on sheet EXPANSION_CONNECTORS
SB1 SB2 = MCD-02162: Solder Bridge 0402 OFF; Part_Type: Misc; Manufacturer_Part_Number: RC0402JR-070RL; Manufacturer: YAGEO; Part_Preference: Recommended; Order_Code_RS: 618-5804; Component_Country_Of_Origin: China; ShowFields: YES; ID: 4262
SB3 = MCD-02162: as SB10 on sheet EXPANSION_CONNECTORS
U1-U3 = MCD-00170: ESD protection 6V1; Part_Type: Diode; Manufacturer: STMICROELECTRONICS; BMS_Part_Number: 9151132; Part_Preference: Recommended; Manufacturer_HQ_COO: EU; Component_Country_Of_Origin: China
U4 = MCD-00264: Dual bit dual supply bus transceiver; Part_Type: IC; Manufacturer: TEXAS INSTRUMENTS; BMS_Part_Number: 9169311; Part_Preference: Recommended; Component_Country_Of_Origin: Thailand
U5 = MCD-00265: Low-Power, Stereo Codec with Headphone Amp; Manufacturer: CIRRUS LOGIC; Part_Type: IC; Part_Preference: Recommended; Component_Country_Of_Origin: China
U6 = MCD-00247: Quad Bidir ESD protection; Manufacturer: STMICROELECTRONICS; Part_Type: Diode; BMS_Part_Number: 9179038; Part_Preference: Recommended; Manufacturer_HQ_COO: EU; Component_Country_Of_Origin: China

## Sheet BOARD_POWER.SchDoc: BOARD Power
size A4; Date: Not used; ApprovedBy: Not used; CheckedBy: Not used; Author: Not used; CompanyName: STMicroelectronics; DrawnBy: Not used; Engineer: Not used; Organization: Not used; Address1: Not used; Address2: Not used; Address3: Not used; Address4: Not used; DocumentNumber: Not used; Revision: Not used; SheetNumber: 14; SheetTotal: 16
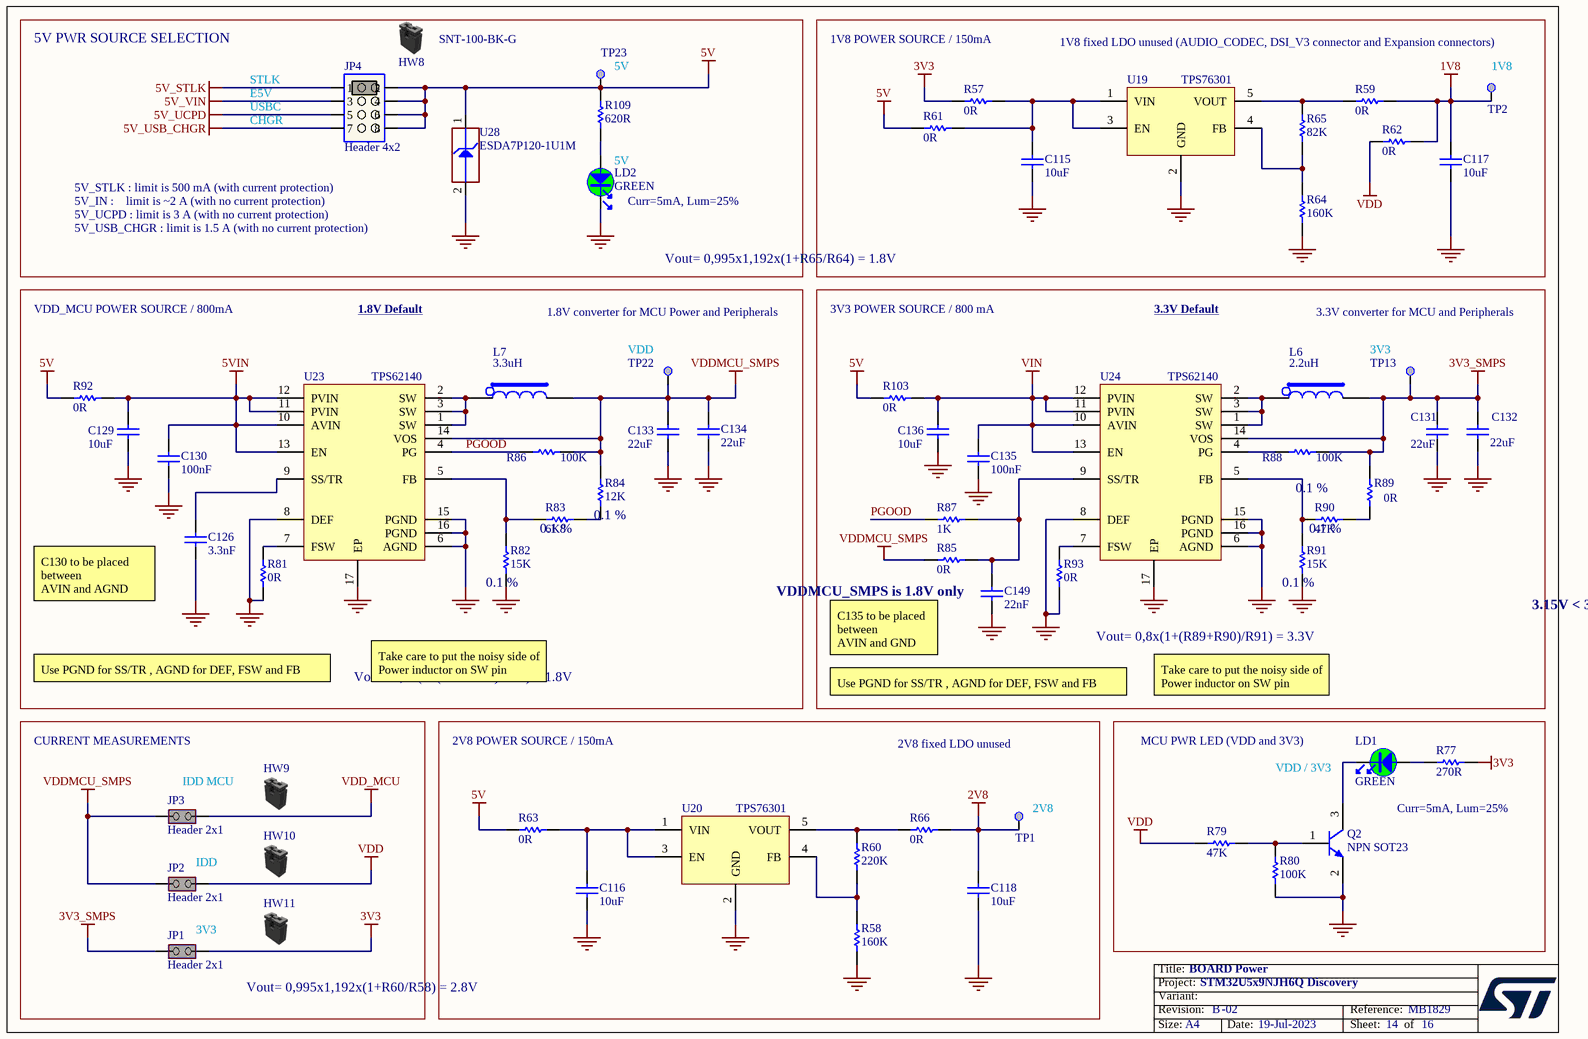
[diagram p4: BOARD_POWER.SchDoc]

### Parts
C115  value 10uF  [C0603_H0P8]  (hidden comment: Capacitor)
C116  value 10uF  [C0603_H0P8]  (hidden comment: Capacitor)
C117  value 10uF  [C0603_H0P8]  (hidden comment: Capacitor)
C118  value 10uF  [C0603_H0P8]  (hidden comment: Capacitor)
C126  value 3.3nF  [C0402]  (hidden comment: Capacitor)
C129  value 10uF  [C1206_H1P6]  (hidden comment: Capacitor)
C130  value 100nF  [C0402]  (hidden comment: Capacitor)
C131  value 22uF  [C0603_H0P8]  (hidden comment: Capacitor)
C132  value 22uF  [C0603_H0P8]  (hidden comment: Capacitor)
C133  value 22uF  [C0603_H0P8]  (hidden comment: Capacitor)
C134  value 22uF  [C0603_H0P8]  (hidden comment: Capacitor)
C135  value 100nF  [C0402]  (hidden comment: Capacitor)
C136  value 10uF  [C1206_H1P6]  (hidden comment: Capacitor)
C149  value 22nF  [C0402]  (hidden comment: Capacitor)
HW8  value SNT-100-BK-G  (hidden comment: Shunt Black 2.54mm)  (mechanical)
HW9  Shunt Black 2.54mm  (value not drawn)  (mechanical)
HW10  Shunt Black 2.54mm  (value not drawn)  (mechanical)
HW11  Shunt Black 2.54mm  (value not drawn)  (mechanical)
JP1  value Header 2x1  [CON_SAMTEC_TSW-102-07-G-S]  (hidden comment: Jumper_Header 2x1 Fitted)
JP2  value Header 2x1  [CON_SAMTEC_TSW-102-07-G-S]  (hidden comment: Jumper_Header 2x1 Fitted)
JP3  value Header 2x1  [CON_SAMTEC_TSW-102-07-G-S]  (hidden comment: Jumper_Header 2x1 Fitted)
JP4  value Header 4x2  [CON_SAMTEC_TSW-104-07-X-D]  (hidden comment: Jumper_Header 4x2 Fitted 1-2)
L6  value 2.2uH  [IND_COILCRAFT_XGL4020]  (hidden comment: INDUCTOR_POWER_WINDING)
L7  value 3.3uH  [IND_COILCRAFT_XGL4020]  (hidden comment: INDUCTOR_POWER_WINDING)
LD1  value GREEN  [LED_0603_OSRAM_LG-Q396-PS-35_GREEN_1A2K_H0P4]  (hidden comment: LED_green)
LD2  value GREEN  [LED_0603_OSRAM_LG-Q396-PS-35_GREEN_1A2K_H0P4]  (hidden comment: LED_green)
Q2  value NPN SOT23  [NPN_SOT23]  (hidden comment: 9013-SOT23)
R57  value 0R  [R0402]  (hidden comment: Resistor)
R58  value 160K  [R0402]  (hidden comment: Resistor)
R59  value 0R  [R0603]  (hidden comment: Resistor)
R60  value 220K  [R0402]  (hidden comment: Resistor)
R61  value 0R  [R0402]  (hidden comment: Resistor)
R62  value 0R  [R0603]  (hidden comment: Resistor)
R63  value 0R  [R0402]  (hidden comment: Resistor)
R64  value 160K  [R0402]  (hidden comment: Resistor)
R65  value 82K  [R0402]  (hidden comment: Resistor)
R66  value 0R  [R0603]  (hidden comment: Resistor)
R77  value 270R  [R0402]  (hidden comment: Resistor)
R79  value 47K  [R0603]  (hidden comment: Resistor)
R80  value 100K  [R0603]  (hidden comment: Resistor)
R81  value 0R  [R0402]  (hidden comment: Resistor)
R82  value 15K  [R0402]  (hidden comment: Resistor)
R83  value 6K8  [R0402]  (hidden comment: Resistor)
R84  value 12K  [R0402]  (hidden comment: Resistor)
R85  value 0R  [R0402]  (hidden comment: Resistor)
R86  value 100K  [R0402]  (hidden comment: Resistor)
R87  value 1K  [R0402]  (hidden comment: Resistor)
R88  value 100K  [R0402]  (hidden comment: Resistor)
R89  value 0R  [R0402]  (hidden comment: Resistor)
R90  value 47K  [R0402]  (hidden comment: Resistor)
R91  value 15K  [R0402]  (hidden comment: Resistor)
R92  value 0R  [R0603]  (hidden comment: Resistor)
R93  value 0R  [R0402]  (hidden comment: Resistor)
R103  value 0R  [R0603]  (hidden comment: Resistor)
R109  value 620R  [R0402]  (hidden comment: Resistor)
TP1  Test Point  [TP_SMD_1MM]  (value not drawn)  (no BOM)
TP2  Test Point  [TP_SMD_1MM]  (value not drawn)  (no BOM)
TP13  Test Point  [TP_SMD_1MM]  (value not drawn)  (no BOM)
TP22  Test Point  [TP_SMD_1MM]  (value not drawn)  (no BOM)
TP23  Test Point  [TP_SMD_1MM]  (value not drawn)  (no BOM)
U19  TPS76301  [ICC_SOT23-5L_H1P45]
U20  TPS76301  [ICC_SOT23-5L_H1P45]
U23  value TPS62140  [ICC_VQFN16-EPAD_3X3_P050]  (hidden comment: TPS62140RGTR)
U24  value TPS62140  [ICC_VQFN16-EPAD_3X3_P050]  (hidden comment: TPS62140RGTR)
U28  value ESDA7P120-1U1M  [ESD_QFN1610_2N_1K_2A]  (hidden comment: ESD-TRANSIL)

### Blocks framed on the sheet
5V PWR SOURCE SELECTION: JP4 LD2 R109 TP23 U28
Vout= 0,995x1,192x(1+R65/R64) = 1.8V: C115 C117 R57 R59 R61 R62 R64 R65 TP2 U19
VDDMCU_SMPS is 1.8V only: C126 C129 C130 C133 C134 L7 R81-R84 R86 R92 TP22 U23
3.15V < 3V3_SMPS typ. < 3.6V: C131 C132 C135 C136 C149 L6 R85 R87-R91 R93 R103 TP13 U24
Vout= 0,995x1,192x(1+R60/R58) = 2.8V: C116 C118 R58 R60 R63 R66 TP1 U20

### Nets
1V8: C117.2 R59.2 R62.2 TP2.1
2V8: C118.2 R66.2 TP1.1
3V3: JP1.2(NO) R57.1 R77.2
3V3_SMPS: C131.1 C132.2 JP1.1(COMMON) L6.2 R88.2 R89.2 TP13.1 U24.14(VOS)
5V: JP4.2 JP4.4 JP4.6 JP4.8 R61.1 R63.1 R92.1 R103.1 R109.2 TP23.1 U28.1(IO1)
5V_STLK: JP4.1
5V_UCPD: JP4.5
5V_USB_CHGR: JP4.7
5V_VIN: JP4.3
5VIN: C129.2 C130.2 R92.2 U23.10(AVIN) U23.11(PVIN) U23.12(PVIN) U23.13(EN)
GND: C115.1 C116.1 C117.1 C118.1 C126.1 C129.1 C130.1 C131.2 C132.1 C133.1 C134.1 C135.1 C136.1 C149.1 LD2.2 Q2.2(E) R58.1 R64.1 R80.1 R81.1 R82.1 R91.1 R93.1 U19.2(GND) U20.2(GND) U23.6(AGND) U23.8(DEF) U23.15(PGND) U23.16(PGND) U23.17(EP) U24.6(AGND) U24.8(DEF) U24.15(PGND) U24.16(PGND) U24.17(EP) U28.2(GND)
VDD: JP2.2(NO) R62.1 R79.1
VDD_MCU: JP3.2(NO)
VDDMCU_SMPS: C133.2 C134.2 JP2.1(COMMON) JP3.1(COMMON) L7.2 R84.1 R85.2 R86.2 TP22.1 U23.14(VOS)
VIN: C135.2 C136.2 R103.2 U24.10(AVIN) U24.11(PVIN) U24.12(PVIN) U24.13(EN)
PGOOD: R86.1 R87.2 U23.4(PG)
NetC115_2: C115.2 R57.2 R61.2 U19.1(VIN) U19.3(EN)
NetC116_2: C116.2 R63.2 U20.1(VIN) U20.3(EN)
NetC126_2: C126.2 U23.9(SS/TR)
NetC149_2: C149.2 R85.1 R87.1 U24.9(SS/TR)
NetL6_1: L6.1 U24.1(SW) U24.2(SW) U24.3(SW)
NetL7_1: L7.1 U23.1(SW) U23.2(SW) U23.3(SW)
NetLD1_1: LD1.1 R77.1
NetLD1_2: LD1.2 Q2.3(C)
NetLD2_1: LD2.1 R109.1
NetQ2_1: Q2.1(B) R79.2 R80.2
NetR58_2: R58.2 R60.1 U20.4(FB)
NetR59_1: R59.1 R65.2 U19.5(VOUT)
NetR60_2: R60.2 R66.1 U20.5(VOUT)
NetR64_2: R64.2 R65.1 U19.4(FB)
NetR81_2: R81.2 U23.7(FSW)
NetR82_2: R82.2 R83.1 U23.5(FB)
NetR83_2: R83.2 R84.2
NetR88_1: R88.1 U24.4(PG)
NetR89_1: R89.1 R90.2
NetR90_1: R90.1 R91.2 U24.5(FB)
NetR93_2: R93.2 U24.7(FSW)

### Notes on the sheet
- 1V8 POWER SOURCE / 150mA
- 1V8 fixed LDO unused (AUDIO_CODEC, DSI_V3 connector and Expansion connectors)
- STLK
- E5V
- USBC
- (near TP23) 5V
- (near TP2) 1V8
- CHGR
- (near LD2) 5V
- 5V_STLK : limit is 500 mA (with current protection)
- 5V_IN :    limit is | A (with no current protection)
- 5V_UCPD : limit is 3 A (with no current protection)
- 5V_USB_CHGR : limit is 1.5 A (with no current protection)
- (near LD2) Curr=5mA, Lum=25%
- VDD_MCU POWER SOURCE / 800mA
- 1.8V Default
- 1.8V converter for MCU Power and Peripherals
- 3V3 POWER SOURCE / 800 mA
- 3.3V Default
- 3.3V converter for MCU and Peripherals
- (near TP22) VDD
- (near TP13) 3V3
- (near R83) 0.1 %
- (near R84) 0.1 %
- (near R89) 0.1 %
- (near R90) 0.1 %
- (near R82) 0.1 %
- (near R91) 0.1 %
- (near C126) C130 to be placed between
  AVIN and AGND
- C135 to be placed between
  AVIN and GND
- Vout= 0,8x(1+(R89+R90)/R91) = 3.3V
- Use PGND for SS/TR , AGND for DEF, FSW and FB
- Take care to put the noisy side of Power inductor on SW pin
- Vout= 0,8x(1+(R83+R84)/R82) = 1.8V
- CURRENT MEASUREMENTS
- IDD MCU
- 2V8 POWER SOURCE / 150mA
- 2V8 fixed LDO unused
- MCU PWR LED (VDD and 3V3)
- VDD / 3V3
- (near TP1) 2V8
- Curr=5mA, Lum=25%
- (near JP2) IDD
- (near JP1) 3V3

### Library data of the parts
C115-C118 = MCD-02605: Capacitor, MLCC, 10uF, 10V, X5R, +/-10%, 0603, T=0.8mm; Part_Preference: Recommended; Manufacturer: YAGEO; Manufacturer_Part_Number: CC0603KRX5R6BB106; Order_Code_RS: 2006536
C126 = MCD-02628: Capacitor, MLCC, 3.3nF, 50V, X7R, +/-10%, 0402, T=0.5mm; Part_Preference: Recommended; Manufacturer: YAGEO; Manufacturer_Part_Number: CC0402KRX7R9BB332; Order_Code_RS: 1992260
C129 C136 = MCD-02610: Capacitor, MLCC, 10uF, 25V, X5R, +/-10%, 1206, T=1.6mm; Part_Preference: Recommended; Manufacturer: YAGEO; Manufacturer_Part_Number: CC1206KKX5R8BB106; Order_Code_RS: 1991983
C130 C135 = MCD-00006: Capacitor, MLCC, 100nF, 16V, X7R, +/-10%, 0402, T=0.5mm; Part_Preference: Recommended; Manufacturer: YAGEO; Manufacturer_Part_Number: CC0402KRX7R7BB104; Order_Code_RS: 616-9701; Component_Country_Of_Origin: China
C131-C134 = MCD-02607: Capacitor, MLCC, 22uF, 10V, X5R, +/-20%, 0603, T=0.8mm; Part_Preference: Recommended; Manufacturer: YAGEO; Manufacturer_Part_Number: CC0603MRX5R6BB226; Order_Code_RS: 2006627
C149 = MCD-03051: Capacitor, MLCC, 22nF, 50V, X7R, +/-10%, 0402, T=0.5mm; Part_Preference: Recommended; Manufacturer: YAGEO; Manufacturer_Part_Number: CC0402KRX7R9BB223; Order_Code_RS: NA; ShowFields: YES; ID: 5167
HW8 = MCD-00043: SHUNT 2.54mm BLACK; Part_Type: Misc; Manufacturer: SAMTEC; Part_Preference: Recommended; Component_Country_Of_Origin: China, Costa Rica, Malaysia, United States, Vietnam
HW9-HW11 = MCD-00043: SHUNT 2.54mm BLACK; Part_Type: Misc; Manufacturer: SAMTEC; Part_Preference: Recommended; Value: SNT-100-BK-G; Component_Country_Of_Origin: China, Costa Rica, Malaysia, United States, Vietnam
JP1-JP3 = MCD-00683: Header, 2x1, 2.54mm, VR, TH, T=5.84mm/2.54mm; Part_Type: Connector; Manufacturer: SAMTEC; Manufacturer_Part_Number: TSW-102-07-G-S; Part_Preference: Recommended; Order_Code_RS: 155-5312; Component_Country_Of_Origin: China, Costa Rica, Malaysia, United States, Vietnam
JP4 = MCD-00686: Header, 4x2, 2.54mm, VR, TH, T=5.84mm/2.54mm; Part_Type: Connector; Manufacturer_Part_Number: TSW-104-07-G-D; Manufacturer: SAMTEC; Part_Preference: Recommended; Order_Code_RS: 161-2260; Component_Country_Of_Origin: China, Costa Rica, Malaysia, United States, Vietnam
L6 = MCD-02582: Inductor, 2.2uH, +/-20%, 8.9A, 0R022, 4x4mm, T=2.1mm; Part_Preference: Recommended; Manufacturer: COILCRAFT; Manufacturer_Part_Number: XGL4020-222MED; ShowFields: YES; ID: 4688
L7 = MCD-02581: Inductor, 3.3uH, +/-20%, 6.6A, 0R034, 4x4mm, T=2.1mm; Part_Preference: Recommended; Manufacturer: COILCRAFT; Manufacturer_Part_Number: XGL4020-332MED; ShowFields: YES; ID: 4687
LD1 LD2 = MCD-00588: LED Green, 0603 SMD, Forward Voltage Typ=2V, Max=2.5V; Part_Type: Display; Manufacturer: OSRAM OPTO SEMICONDUCTORS; Manufacturer_Part_Number: LG Q396-PS-35; Part_Preference: Recommended; Alternate_Internal_Part_Number: MCD-02400; Component_Country_Of_Origin: Unknown; ShowFields: YES; ID: 3155
Q2 = MCD-00073: NPN Bipolar Transistor; Part_Type: IC; Manufacturer_Part_Number: BSR14; Manufacturer: ON SEMICONDUCTOR; Part_Preference: Recommended; Component_Country_Of_Origin: Unknown
R57 R61 R63 R81 R85 R93 = MCD-00052: Resistor, 0R, 0402, +/-5%, 1/16W; Part_Preference: Recommended; Manufacturer: YAGEO; Manufacturer_Part_Number: RC0402JR-070RL; Order_Code_RS: 618-5804; Component_Country_Of_Origin: China
R58 R64 = MCD-00405: Resistor, 160K, 0402, +/-1%, 1/16W; Part_Preference: Recommended; Manufacturer: YAGEO; Manufacturer_Part_Number: RC0402FR-07160KL; Component_Country_Of_Origin: China
R59 R62 R66 R92 R103 = MCD-00181: Resistor, 0R, 0603, +/- 0.5mR, 1/4W; Part_Preference: Recommended; Manufacturer: ROHM; Manufacturer_Part_Number: PMR03EZPJ000; Component_Country_Of_Origin: Philippines, Thailand
R60 = MCD-00164: Resistor, 220K, 0402, +/-1%, 1/16W; Part_Preference: Recommended; Manufacturer: YAGEO; Manufacturer_Part_Number: RC0402FR-07220KL; Component_Country_Of_Origin: China
R65 = MCD-00531: Resistor, 82K, 0402, +/-1%, 1/16W; Part_Preference: Recommended; Manufacturer: YAGEO; Manufacturer_Part_Number: RC0402FR-0782KL; Component_Country_Of_Origin: China
R77 = MCD-00441: Resistor, 270R, 0402, +/-1%, 1/16W; Manufacturer: YAGEO; Manufacturer_Part_Number: RC0402FR-07270RL; Part_Preference: Recommended; Component_Country_Of_Origin: China; ShowFields: YES; ID: 2838
R79 = MCD-00222: Resistor, 47K, 0603, 1%, 1/10W; Manufacturer_Part_Number: RC0603FR-0747KL; Manufacturer: YAGEO; Part_Preference: Recommended; Component_Country_Of_Origin: China
R80 = MCD-00223: Resistor, 100K, 0603, +/- 1%, 1/10W; Manufacturer_Part_Number: RC0603FR-07100KL; Manufacturer: YAGEO; Part_Preference: Recommended; Component_Country_Of_Origin: China
R82 R91 = MCD-02570: Resistor, 15K, 0402, +/-0.1%, 1/16W, +/-25ppm/°C; Part_Preference: Recommended; Manufacturer: YAGEO; Manufacturer_Part_Number: RT0402BRD0715KL; Order_Code_RS: 1991284
R83 = MCD-02568: Resistor, 6K8, 0402, +/-0.1%, 1/16W, +/-25ppm/°C; Part_Preference: Recommended; Manufacturer: YAGEO; Manufacturer_Part_Number: RT0402BRD076K8L; Order_Code_RS: 1991364
R84 = MCD-02567: Resistor, 12K, 0402, +/-0.1%, 1/16W, +/-25ppm/°C; Part_Preference: Recommended; Manufacturer: YAGEO; Manufacturer_Part_Number: RT0402BRD0712KL
R86 R88 = MCD-00059: Resistor, 100K, 0402, +/-1%, 1/16W; Part_Preference: Recommended; Manufacturer: YAGEO; Manufacturer_Part_Number: RC0402FR-07100KL; Component_Country_Of_Origin: China
R87 = MCD-00061: Resistor, 1K, 0402, +/-1%,1/16W; Part_Preference: Recommended; Manufacturer: YAGEO; Manufacturer_Part_Number: RC0402FR-071KL; Component_Country_Of_Origin: China; ShowFields: YES; ID: 2532
R89 = MCD-00052: Resistor, 0R, 0402, +/-5%, 1/16W; Part_Preference: Recommended; Manufacturer: YAGEO; Manufacturer_Part_Number: RC0402JR-070RL; Order_Code_RS: 618-5804; Component_Country_Of_Origin: China; ShowFields: YES; ID: 2540
R90 = MCD-02550: Resistor, 47K, 0402, +/-0.1%, 1/16W, +/-25ppm/°C; Part_Preference: Recommended; Manufacturer: YAGEO; Manufacturer_Part_Number: RT0402BRD0747KL; Order_Code_RS: 1991342
R109 = MCD-00499: Resistor, 620R, 0402, +/-1%, 1/16W; Manufacturer: YAGEO; Manufacturer_Part_Number: RC0402FR-07620RL; Part_Preference: Recommended; Component_Country_Of_Origin: China; ShowFields: YES; ID: 2781
TP1 TP2 TP13 TP22 TP23 = MCD-00074: Test Point 1mm; Part_Type: Misc; Part_Preference: Recommended
U19 U20 = MCD-02175: LDO VOLTAGE REGULATOR, Adjustable, 150mA,; Part_Type: IC; Manufacturer_Part_Number: TPS76301DBVT; Manufacturer: TEXAS INSTRUMENTS; Part_Preference: Recommended; Component_Country_Of_Origin: China
U23 U24 = MCD-02580: Buck converter, 2A, 3V to 17V input, Fsw 1.25/2.5 MHz, 3x3 VQFN16; Part_Type: IC; Part_Preference: Recommended; Manufacturer: TEXAS INSTRUMENTS
U28 = MCD-01026: High power transient voltage suppressor; Part_Type: Diode; Manufacturer: STMICROELECTRONICS; BMS_Part_Number: 9179046; Part_Preference: Recommended; Manufacturer_HQ_COO: EU; Component_Country_Of_Origin: China

## Sheet MCU_CLOCK_AND_USER_INTERFACE.SchDoc: MCU_CLOCK_AND_USER_INTERFACE
size A4; Date: Not used; ApprovedBy: Not used; CheckedBy: Not used; Author: Not used; CompanyName: STMicroelectronics; DrawnBy: Not used; Engineer: Not used; Organization: Not used; Address1: Not used; Address2: Not used; Address3: Not used; Address4: Not used; DocumentNumber: Not used; Revision: Not used; SheetNumber: 4; SheetTotal: 16
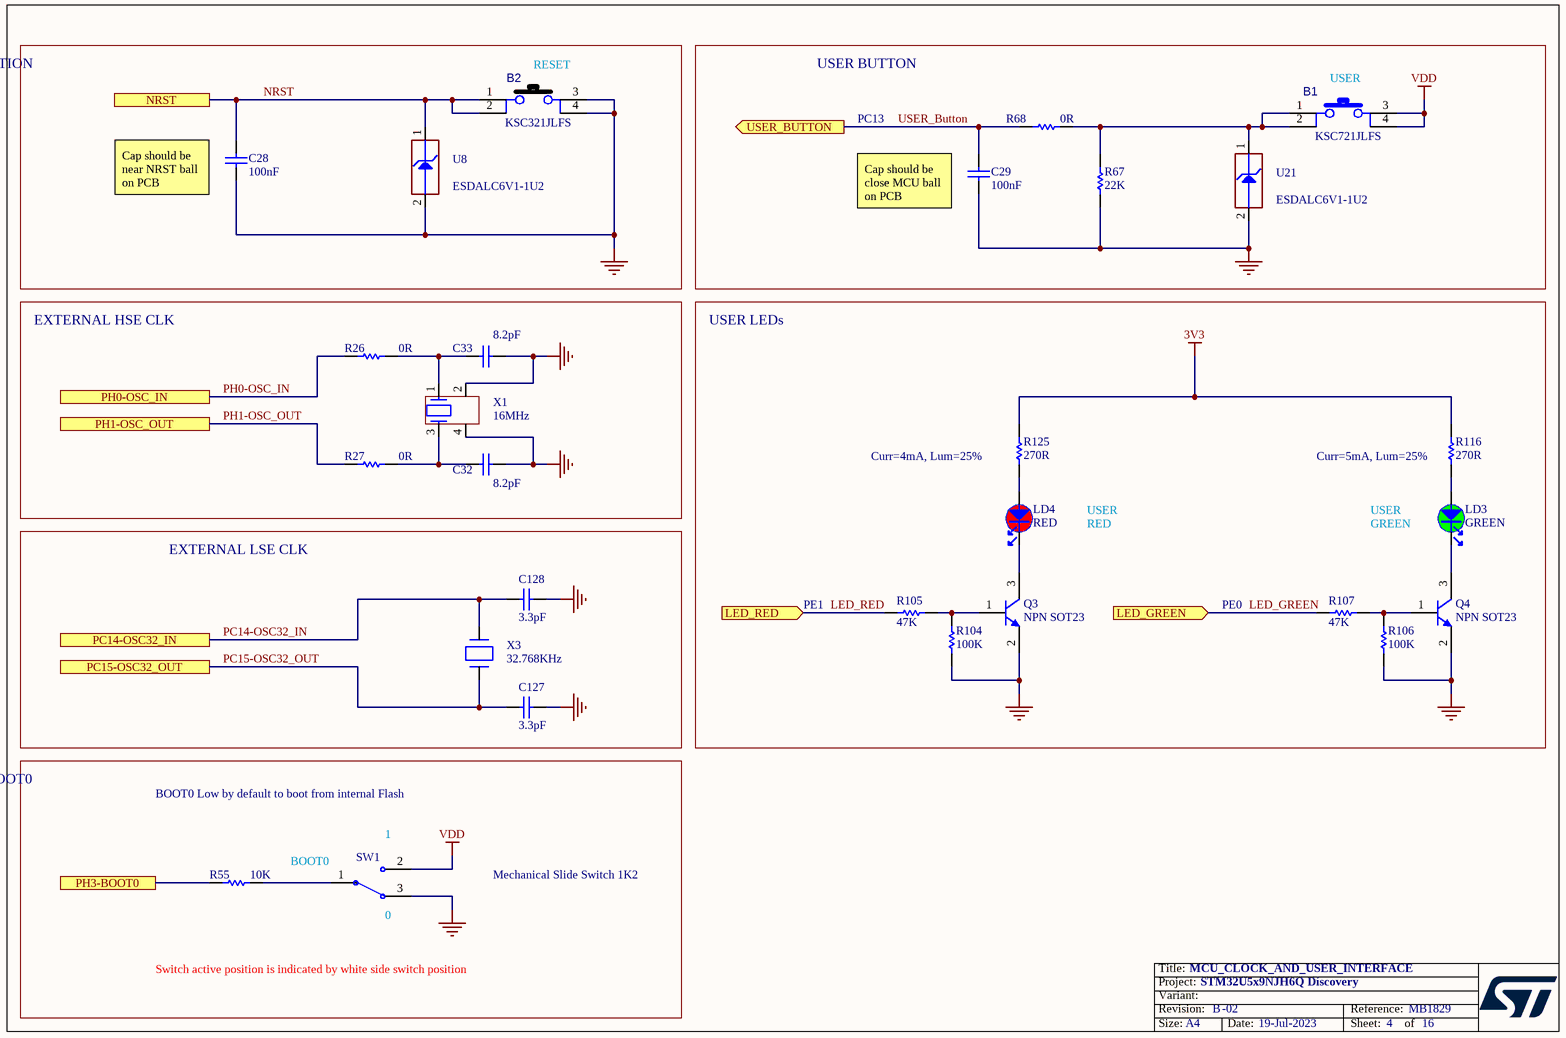
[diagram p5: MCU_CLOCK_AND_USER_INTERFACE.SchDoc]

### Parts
B1  value KSC721JLFS  [SWI_C&K_KSC721JLFS_BLUE]  (hidden comment: SW_BLUE_KSC721JLFS)
B2  value KSC321JLFS  [SWI_C&K_KSC321JLFS_BLACK]  (hidden comment: SW_BLACK_KSC321JLFS)
C28  value 100nF  [C0402]  (hidden comment: Capacitor)
C29  value 100nF  [C0402]  (hidden comment: Capacitor)
C32  value 8.2pF  [C0402]  (hidden comment: Capacitor)
C33  value 8.2pF  [C0402]  (hidden comment: Capacitor)
C127  value 3.3pF  [C0402]  (hidden comment: Capacitor)
C128  value 3.3pF  [C0402]  (hidden comment: Capacitor)
LD3  value GREEN  [LED_0603_OSRAM_LG-Q396-PS-35_GREEN_1A2K_H0P4]  (hidden comment: LED_green)
LD4  value RED  [LED_0603_OSRAM_LS-Q976-NR-1_RED_1A2K_H0P8]  (hidden comment: LED_red)
Q3  value NPN SOT23  [NPN_SOT23]  (hidden comment: 9013-SOT23)
Q4  value NPN SOT23  [NPN_SOT23]  (hidden comment: 9013-SOT23)
R26  value 0R  [R0402]  (hidden comment: Resistor)
R27  value 0R  [R0402]  (hidden comment: Resistor)
R55  value 10K  [R0603]  (hidden comment: Resistor)
R67  value 22K  [R0603]  (hidden comment: Resistor)
R68  value 0R  [R0603]  (hidden comment: Resistor)
R104  value 100K  [R0603]  (hidden comment: Resistor)
R105  value 47K  [R0603]  (hidden comment: Resistor)
R106  value 100K  [R0603]  (hidden comment: Resistor)
R107  value 47K  [R0603]  (hidden comment: Resistor)
R116  value 270R  [R0402]  (hidden comment: Resistor)
R125  value 270R  [R0402]  (hidden comment: Resistor)
SW1  value Mechanical Slide Switch 1K2  [SWI_EAO_09-03290-01_EXTENDED_STRAIGHT_BLACK]  (hidden comment: SW_MECA_1K2)
U8  value ESDALC6V1-1U2  [ESD_ST0201]  (hidden comment: ESD-TRANSIL)
U21  value ESDALC6V1-1U2  [ESD_ST0201]  (hidden comment: ESD-TRANSIL)
X1  value 16MHz  [CRY_NX2016SA_4P]  (hidden comment: XTAL_4_PINS)
X3  value 32.768KHz  [CRY_NX2012SA_2P]  (hidden comment: XTAL_2_PINS)

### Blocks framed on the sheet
RESET FUNCTION: B2 C28 U8
USER BUTTON: B1 C29 R67 R68 U21
EXTERNAL HSE CLK: C32 C33 R26 R27 X1
USER LEDs: LD3 LD4 Q3 Q4 R104-R107 R116 R125
EXTERNAL LSE CLK: C127 C128 X3
PH3_BOOT0: R55 SW1

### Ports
LED_GREEN (in), LED_RED (in), NRST, PC14-OSC32_IN, PC15-OSC32_OUT, PH0-OSC_IN, PH1-OSC_OUT, PH3-BOOT0, USER_BUTTON (out)

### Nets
3V3: R116.2 R125.2
GND: B2.3 B2.4 C28.1 C29.1 C32.2 C33.2 C127.2 C128.2 Q3.2(E) Q4.2(E) R67.1 R104.1 R106.1 SW1.3 U8.2(GND) U21.2(GND) X1.2 X1.4
VDD: B1.3 B1.4 SW1.2
LED_GREEN: R107.1 ; port LED_GREEN
LED_RED: R105.1 ; port LED_RED
NRST: B2.1 B2.2 C28.2 U8.1(IO1) ; port NRST
PC14-OSC32_IN: C128.1 X3.2(X2) ; port PC14-OSC32_IN
PC15-OSC32_OUT: C127.1 X3.1(X1) ; port PC15-OSC32_OUT
PH0-OSC_IN: R26.1 ; port PH0-OSC_IN
PH1-OSC_OUT: R27.1 ; port PH1-OSC_OUT
PH3-BOOT0: R55.1 ; port PH3-BOOT0
USER_Button: C29.2 R68.1 ; port USER_BUTTON
NetB1_1: B1.1 B1.2 R67.2 R68.2 U21.1(IO1)
NetC32_1: C32.1 R27.2 X1.3
NetC33_1: C33.1 R26.2 X1.1
NetLD3_1: LD3.1 R116.1
NetLD3_2: LD3.2 Q4.3(C)
NetLD4_1: LD4.1 R125.1
NetLD4_2: LD4.2 Q3.3(C)
NetQ3_1: Q3.1(B) R104.2 R105.2
NetQ4_1: Q4.1(B) R106.2 R107.2
NetR55_2: R55.2 SW1.1

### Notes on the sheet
- (near B2) RESET
- (near B1) USER
- PC13
- (near C28) Cap should be near NRST ball on PCB
- (near C29) Cap should be close MCU ball on PCB
- Curr=4mA, Lum=25%
- USER
- Curr=5mA, Lum=25%
- RED
- GREEN
- PE1
- PE0
- BOOT0 Low by default to boot from internal Flash
- (near SW1) 1
- BOOT0
- (near SW1) 0
- Switch active position is indicated by white side switch position

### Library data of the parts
B1 = MCD-01800: Switch HW BLUE High4.3mm 2.25 Newtons, BEND type; Part_Type: Misc; Manufacturer: C&K; Part_Preference: Recommended; Component_Country_Of_Origin: France
B2 = MCD-01799: Switch HW BLACK High3.5mm 2Newtons, BEND type; Part_Type: Misc; Manufacturer: C&K; Part_Preference: Recommended; Component_Country_Of_Origin: France
C28 C29 = MCD-00006: as C1 on sheet AUDIO
C32 C33 = MCD-01932: Capacitor, MLCC, 8.2pF, 50V, NPO, +/-0.25pF, 0402, T=0.5mm; Part_Preference: Recommended; Manufacturer: YAGEO; Manufacturer_Part_Number: CC0402CRNPO9BN8R2; Component_Country_Of_Origin: China
C127 C128 = MCD-01775: Capacitor, MLCC, 3.3pF, 50V, NPO, +/-0.1pF, 0402, T=0.5mm; Part_Preference: Recommended; Manufacturer: YAGEO; Manufacturer_Part_Number: CC0402BRNPO9BN3R3; Component_Country_Of_Origin: China
LD3 = MCD-00588: LED Green, 0603 SMD, Forward Voltage Typ=2V, Max=2.5V; Part_Type: Display; Manufacturer_Part_Number: LG Q396-PS-35; Manufacturer: OSRAM OPTO SEMICONDUCTORS; Part_Preference: Recommended; Alternate_Internal_Part_Number: MCD-02400; Component_Country_Of_Origin: Unknown; ShowFields: YES; ID: 3155
LD4 = MCD-00586: LED Red, 0603 SMD, Forward Voltage Typ=2V, Max=2.5V; Manufacturer_Part_Number: LS Q976-NR-1; Manufacturer: OSRAM OPTO SEMICONDUCTORS; Part_Type: Display; Part_Preference: Recommended; Component_Country_Of_Origin: Unknown; ShowFields: YES; ID: 3158
Q3 Q4 = MCD-00073: as Q2 on sheet BOARD_POWER
R26 R27 = MCD-00052: as R2 on sheet AUDIO
R55 = MCD-00220: Resistor, 10K, 0603, +/-1%, 1/10W; Manufacturer_Part_Number: RC0603FR-0710KL; Manufacturer: YAGEO; Part_Preference: Recommended; Component_Country_Of_Origin: China
R67 = MCD-00430: Resistor, 22K, 0603, +/-1%, 1/10W; Manufacturer_Part_Number: RC0603FR-0722KL; Manufacturer: YAGEO; Part_Preference: Recommended; Component_Country_Of_Origin: China; ShowFields: YES; ID: 2847
R68 = MCD-00056: Resistor, 0R, 0603, +/-5%, 1/10W; Manufacturer_Part_Number: RC0603JR-070RL; Manufacturer: YAGEO; Part_Preference: Recommended; Component_Country_Of_Origin: China; ShowFields: YES; ID: 2536
R104 R106 = MCD-00223: as R80 on sheet BOARD_POWER
R105 R107 = MCD-00222: as R79 on sheet BOARD_POWER
R116 = MCD-00441: as R77 on sheet BOARD_POWER
R125 = MCD-00441: Resistor, 270R, 0402, +/-1%, 1/16W; Manufacturer_Part_Number: RC0402FR-07270RL; Manufacturer: YAGEO; Part_Preference: Recommended; Component_Country_Of_Origin: China; ShowFields: YES; ID: 2838
SW1 = MCD-00566: Mechanical Slide Switches 1K2 BLK ACT GOLD STRT MNT; Part_Preference: Recommended; Part_Type: Misc; Manufacturer: EAO; Manufacturer_Part_Number: 09.03290.01; Component_Country_Of_Origin: Switzerland
U8 U21 = MCD-00170: as U1 on sheet AUDIO
X1 = MCD-01476: Crystal, 16 MHz, 8pF, +/-20ppm, 200R, 2x1.6mm; Part_Type: Crystal_Osc; Manufacturer_Part_Number: NX2016SA-16MHZ-EXS00A-CS07826; Manufacturer: NDK; BMS_Part_Number: 9157046; Part_Preference: Recommended; Component_Country_Of_Origin: Unknown
X3 = MCD-01479: Crystal, 32.768kHz, 6pF, +/-20ppm, 80K, 2.05x1.2mm; Part_Type: Crystal_Osc; Manufacturer_Part_Number: NX2012SA-32.768KHZ-EXS00A-MU00527; Manufacturer: NDK; BMS_Part_Number: 9157049; Part_Preference: Recommended; Component_Country_Of_Origin: Unknown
